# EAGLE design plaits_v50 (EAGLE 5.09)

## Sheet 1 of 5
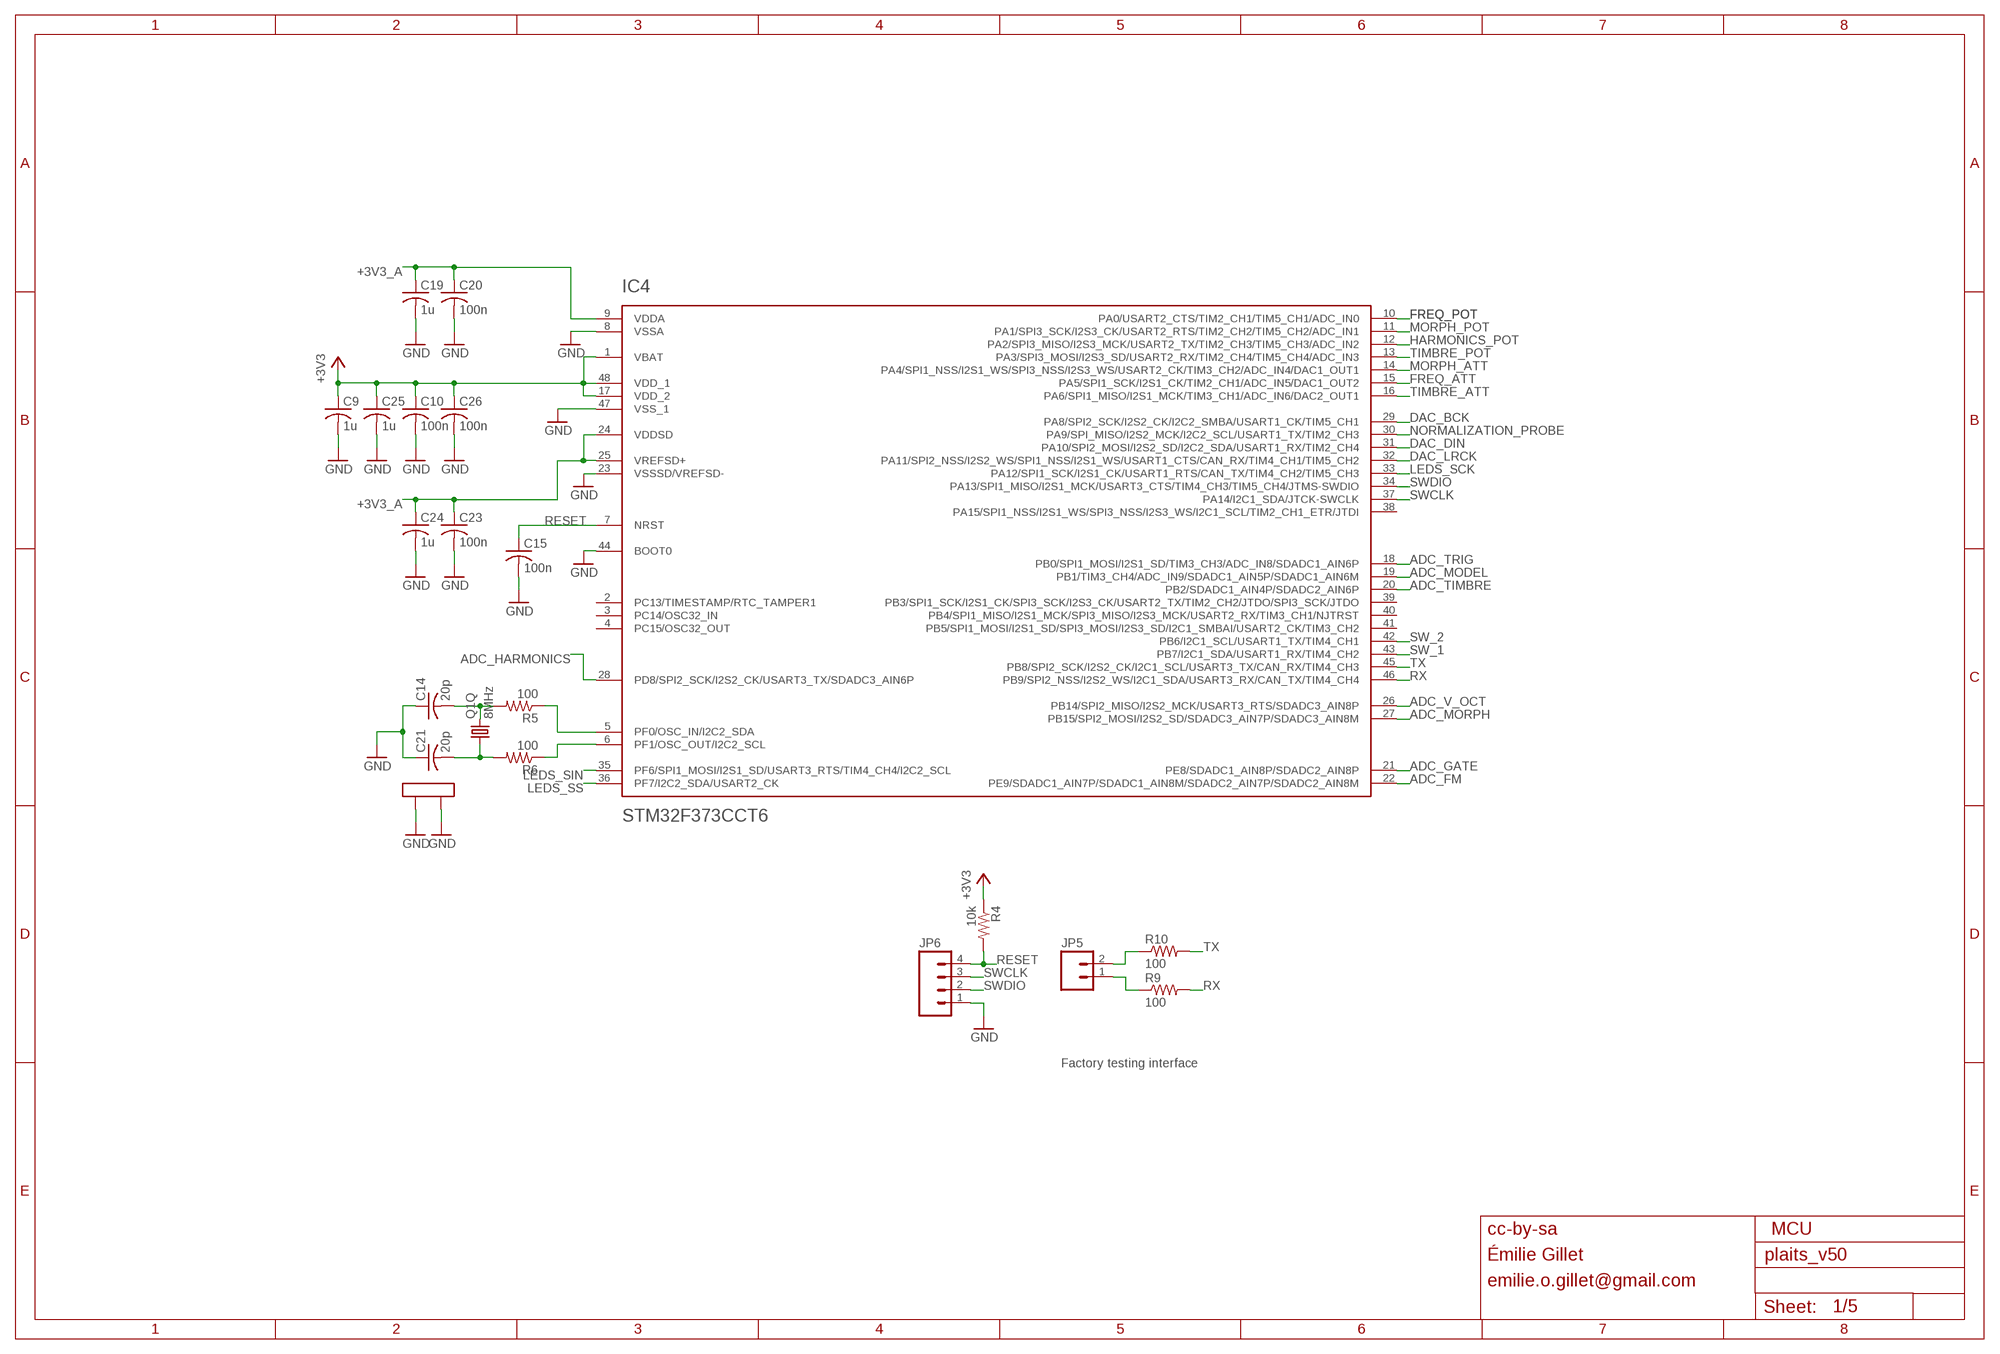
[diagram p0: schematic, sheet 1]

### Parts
C9  1u  C-USC0402  [C0402]
C10  100n  C-USC0402  [C0402]
C14  20p  C-USC0402  [C0402]
C15  100n  C-USC0402  [C0402]
C19  1u  C-USC0402  [C0402]
C20  100n  C-USC0402  [C0402]
C21  20p  C-USC0402  [C0402]
C23  100n  C-USC0402  [C0402]
C24  1u  C-USC0402  [C0402]
C25  1u  C-USC0402  [C0402]
C26  100n  C-USC0402  [C0402]
IC4  STM32F373CCT6  STM32F373C  [LQFP48]
JP5  M02PTH  [1X02]
JP6  M04PTH  [1X04]
Q1  8MHz  CRYSTAL  [CTS406]
R4  10k  R-US_R0402  [R0402]
R5  100  R-US_R0402  [R0402]
R6  100  R-US_R0402  [R0402]
R9  100  R-US_R0402  [R0402]
R10  100  R-US_R0402  [R0402]

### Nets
+3V3: C9.1 C10.1 C25.1 C26.1 IC4.1(VBAT) IC4.17(VDD_2) IC4.48(VDD_1) R4.1 ; also sheet 2,3,4,5
+3V3_A: C19.1 C20.1 C23.1 C24.1 IC4.9(VDDA) IC4.24(VDDSD) IC4.25(VREFSD+) ; also sheet 2,3,4,5
ADC_FM: IC4.22(PE9/SDADC1_AIN7P/SDADC1_AIN8M/SDADC2_AIN7P/SDADC2_AIN8M) ; also sheet 3
ADC_GATE: IC4.21(PE8/SDADC1_AIN8P/SDADC2_AIN8P) ; also sheet 3
ADC_HARMONICS: IC4.28(PD8/SPI2_SCK/I2S2_CK/USART3_TX/SDADC3_AIN6P) ; also sheet 3
ADC_MODEL: IC4.19(PB1/TIM3_CH4/ADC_IN9/SDADC1_AIN5P/SDADC1_AIN6M) ; also sheet 3
ADC_MORPH: IC4.27(PB15/SPI2_MOSI/I2S2_SD/SDADC3_AIN7P/SDADC3_AIN8M) ; also sheet 3
ADC_TIMBRE: IC4.20(PB2/SDADC1_AIN4P/SDADC2_AIN6P) ; also sheet 3
ADC_TRIG: IC4.18(PB0/SPI1_MOSI/I2S1_SD/TIM3_CH3/ADC_IN8/SDADC1_AIN6P) ; also sheet 3
ADC_V_OCT: IC4.26(PB14/SPI2_MISO/I2S2_MCK/USART3_RTS/SDADC3_AIN8P) ; also sheet 3
DAC_BCK: IC4.29(PA8/SPI2_SCK/I2S2_CK/I2C2_SMBA/USART1_CK/TIM5_CH1) ; also sheet 4
DAC_DIN: IC4.31(PA10/SPI2_MOSI/I2S2_SD/I2C2_SDA/USART1_RX/TIM2_CH4) ; also sheet 4
DAC_LRCK: IC4.32(PA11/SPI2_NSS/I2S2_WS/SPI1_NSS/I2S1_WS/USART1_CTS/CAN_RX/TIM4_CH1/TIM5_CH2) ; also sheet 4
FREQ_ATT: IC4.15(PA5/SPI1_SCK/I2S1_CK/TIM2_CH1/ADC_IN5/DAC1_OUT2) ; also sheet 2
FREQ_POT: IC4.10(PA0/USART2_CTS/TIM2_CH1/TIM5_CH1/ADC_IN0) ; also sheet 2
GND: C9.2 C10.2 C14.1 C15.2 C19.2 C20.2 C21.1 C23.2 C24.2 C25.2 C26.2 IC4.8(VSSA) IC4.23(VSSSD/VREFSD-) IC4.44(BOOT0) IC4.47(VSS_1) JP6.1 Q1.2(LID1) Q1.4(LID2) ; also sheet 2,3,4,5
HARMONICS_POT: IC4.12(PA2/SPI3_MISO/I2S3_MCK/USART2_TX/TIM2_CH3/TIM5_CH3/ADC_IN2) ; also sheet 2
LEDS_SCK: IC4.33(PA12/SPI1_SCK/I2S1_CK/USART1_RTS/CAN_TX/TIM4_CH2/TIM5_CH3) ; also sheet 2
LEDS_SIN: IC4.35(PF6/SPI1_MOSI/I2S1_SD/USART3_RTS/TIM4_CH4/I2C2_SCL) ; also sheet 2
LEDS_SS: IC4.36(PF7/I2C2_SDA/USART2_CK) ; also sheet 2
MORPH_ATT: IC4.14(PA4/SPI1_NSS/I2S1_WS/SPI3_NSS/I2S3_WS/USART2_CK/TIM3_CH2/ADC_IN4/DAC1_OUT1) ; also sheet 2
MORPH_POT: IC4.11(PA1/SPI3_SCK/I2S3_CK/USART2_RTS/TIM2_CH2/TIM5_CH2/ADC_IN1) ; also sheet 2
N$7: IC4.5(PF0/OSC_IN/I2C2_SDA) R5.1
N$8: IC4.6(PF1/OSC_OUT/I2C2_SCL) R6.1
N$29: C14.2 Q1.3 R5.2
N$33: JP5.2 R10.1
N$35: C21.2 Q1.1 R6.2
N$51: JP5.1 R9.1
NORMALIZATION_PROBE: IC4.30(PA9/SPI_MISO/I2S2_MCK/I2C2_SCL/USART1_TX/TIM2_CH3) ; also sheet 3
RESET: C15.1 IC4.7(NRST) JP6.4 R4.2
RX: IC4.46(PB9/SPI2_NSS/I2S2_WS/I2C1_SDA/USART3_RX/CAN_TX/TIM4_CH4) R9.2
SW_1: IC4.43(PB7/I2C1_SDA/USART1_RX/TIM4_CH2) ; also sheet 2
SW_2: IC4.42(PB6/I2C1_SCL/USART1_TX/TIM4_CH1) ; also sheet 2
SWCLK: IC4.37(PA14/I2C1_SDA/JTCK-SWCLK) JP6.3
SWDIO: IC4.34(PA13/SPI1_MISO/I2S1_MCK/USART3_CTS/TIM4_CH3/TIM5_CH4/JTMS-SWDIO) JP6.2
TIMBRE_ATT: IC4.16(PA6/SPI1_MISO/I2S1_MCK/TIM3_CH1/ADC_IN6/DAC2_OUT1) ; also sheet 2
TIMBRE_POT: IC4.13(PA3/SPI3_MOSI/I2S3_SD/USART2_RX/TIM2_CH4/TIM5_CH4/ADC_IN3) ; also sheet 2
TX: IC4.45(PB8/SPI2_SCK/I2S2_CK/I2C1_SCL/USART3_TX/CAN_RX/TIM4_CH3) R10.2
Unconnected: IC4.2(PC13/TIMESTAMP/RTC_TAMPER1) IC4.3(PC14/OSC32_IN) IC4.4(PC15/OSC32_OUT) IC4.38(PA15/SPI1_NSS/I2S1_WS/SPI3_NSS/I2S3_WS/I2C1_SCL/TIM2_CH1_ETR/JTDI) IC4.39(PB3/SPI1_SCK/I2S1_CK/SPI3_SCK/I2S3_CK/USART2_TX/TIM2_CH2/JTDO/SPI3_SCK/JTDO) IC4.40(PB4/SPI1_MISO/I2S1_MCK/SPI3_MISO/I2S3_MCK/USART2_RX/TIM3_CH1/NJTRST) IC4.41(PB5/SPI1_MOSI/I2S1_SD/SPI3_MOSI/I2S3_SD/I2C1_SMBAI/USART2_CK/TIM3_CH2)

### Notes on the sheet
- Factory testing interface
- cc-by-sa | MCU
- Émilie Gillet
- emilie.o.gillet@gmail.com

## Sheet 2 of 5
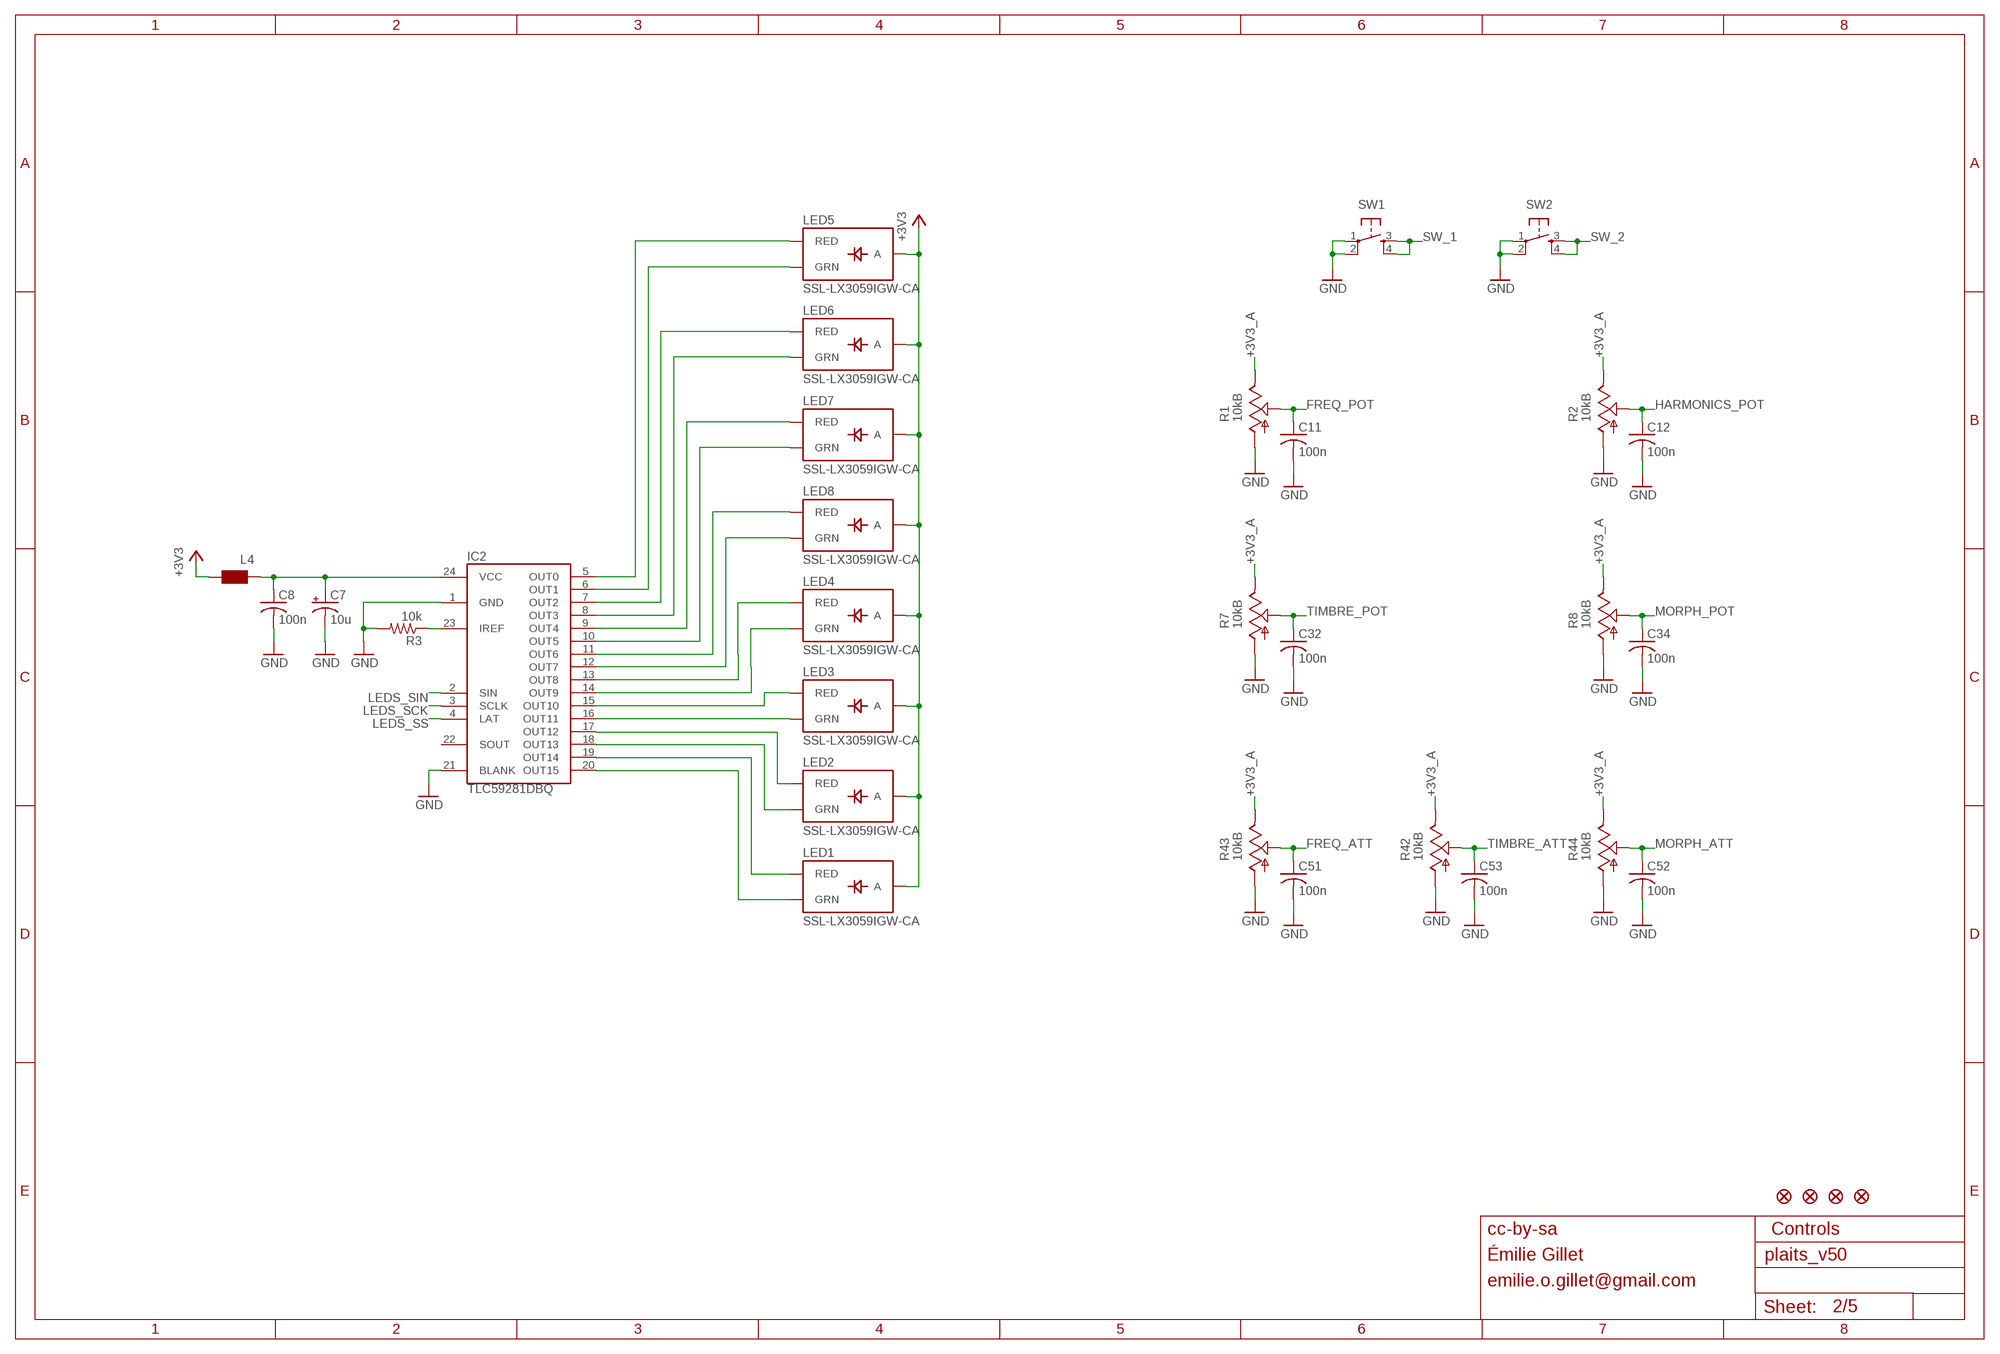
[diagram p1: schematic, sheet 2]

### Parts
C7  10u  CPOL-USA  [PANASONIC_A]
C8  100n  C-USC0402  [C0402]
C11  100n  C-USC0402  [C0402]
C12  100n  C-USC0402  [C0402]
C32  100n  C-USC0402  [C0402]
C34  100n  C-USC0402  [C0402]
C51  100n  C-USC0402  [C0402]
C52  100n  C-USC0402  [C0402]
C53  100n  C-USC0402  [C0402]
IC2  TLC59281DBQ  [TSSOP24_0635]
JP1  FIDUCIAL1X2  [FIDUCIAL-1X2]
JP2  FIDUCIAL1X2  [FIDUCIAL-1X2]
JP3  FIDUCIAL1X2  [FIDUCIAL-1X2]
JP4  FIDUCIAL1X2  [FIDUCIAL-1X2]
L4  WE-CBF_0603  [0603]
LED1  SSL-LX3059IGW-CA  LED-BICOLOR-THROUGHHOLE-CA  [LED-BICOLOR-THROUGHHOLE-LUMEX]
LED2  SSL-LX3059IGW-CA  LED-BICOLOR-THROUGHHOLE-CA  [LED-BICOLOR-THROUGHHOLE-LUMEX]
LED3  SSL-LX3059IGW-CA  LED-BICOLOR-THROUGHHOLE-CA  [LED-BICOLOR-THROUGHHOLE-LUMEX]
LED4  SSL-LX3059IGW-CA  LED-BICOLOR-THROUGHHOLE-CA  [LED-BICOLOR-THROUGHHOLE-LUMEX]
LED5  SSL-LX3059IGW-CA  LED-BICOLOR-THROUGHHOLE-CA  [LED-BICOLOR-THROUGHHOLE-LUMEX]
LED6  SSL-LX3059IGW-CA  LED-BICOLOR-THROUGHHOLE-CA  [LED-BICOLOR-THROUGHHOLE-LUMEX]
LED7  SSL-LX3059IGW-CA  LED-BICOLOR-THROUGHHOLE-CA  [LED-BICOLOR-THROUGHHOLE-LUMEX]
LED8  SSL-LX3059IGW-CA  LED-BICOLOR-THROUGHHOLE-CA  [LED-BICOLOR-THROUGHHOLE-LUMEX]
R1  10kB  POT_USVERTICAL_PS  [ALPS_POT_VERTICAL_PS]
R2  10kB  POT_USVERTICAL_PS  [ALPS_POT_VERTICAL_PS]
R3  10k  R-US_R0402  [R0402]
R7  10kB  POT_USVERTICAL_PS  [ALPS_POT_VERTICAL_PS]
R8  10kB  POT_USVERTICAL_PS  [ALPS_POT_VERTICAL_PS]
R42  10kB  POT_USVERTICAL  [ALPS_POT_VERTICAL]
R43  10kB  POT_USVERTICAL  [ALPS_POT_VERTICAL]
R44  10kB  POT_USVERTICAL  [ALPS_POT_VERTICAL]
SW1  TAC_SWITCHPTH  [TACTILE-PTH]
SW2  TAC_SWITCHPTH  [TACTILE-PTH]

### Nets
+3V3: L4.2 LED1.A LED2.A LED3.A LED4.A LED5.A LED6.A LED7.A LED8.A ; also sheet 1,3,4,5
+3V3_A: R1.P$1(E) R2.P$1(E) R7.P$1(E) R8.P$1(E) R42.P$1(E) R43.P$1(E) R44.P$1(E) ; also sheet 1,3,4,5
FREQ_ATT: C51.1 R43.P$2(S) ; also sheet 1
FREQ_POT: C11.1 R1.P$2(S) ; also sheet 1
GND: C7.- C8.2 C11.2 C12.2 C32.2 C34.2 C51.2 C52.2 C53.2 IC2.1(GND) IC2.21(BLANK) R1.P$3(A) R2.P$3(A) R3.2 R7.P$3(A) R8.P$3(A) R42.P$3(A) R43.P$3(A) R44.P$3(A) SW1.1 SW1.2 SW2.1 SW2.2 ; also sheet 1,3,4,5
HARMONICS_POT: C12.1 R2.P$2(S) ; also sheet 1
LEDS_SCK: IC2.3(SCLK) ; also sheet 1
LEDS_SIN: IC2.2(SIN) ; also sheet 1
LEDS_SS: IC2.4(LAT) ; also sheet 1
MORPH_ATT: C52.1 R44.P$2(S) ; also sheet 1
MORPH_POT: C34.1 R8.P$2(S) ; also sheet 1
N$2: IC2.12(OUT7) LED8.GREEN_C(GRN)
N$5: IC2.11(OUT6) LED8.RED_C(RED)
N$9: IC2.10(OUT5) LED7.GREEN_C(GRN)
N$10: IC2.9(OUT4) LED7.RED_C(RED)
N$11: IC2.8(OUT3) LED6.GREEN_C(GRN)
N$12: IC2.13(OUT8) LED4.RED_C(RED)
N$13: IC2.7(OUT2) LED6.RED_C(RED)
N$14: IC2.14(OUT9) LED4.GREEN_C(GRN)
N$15: IC2.6(OUT1) LED5.GREEN_C(GRN)
N$17: IC2.15(OUT10) LED3.RED_C(RED)
N$18: IC2.16(OUT11) LED3.GREEN_C(GRN)
N$19: IC2.17(OUT12) LED2.RED_C(RED)
N$20: IC2.18(OUT13) LED2.GREEN_C(GRN)
N$21: IC2.19(OUT14) LED1.RED_C(RED)
N$22: IC2.5(OUT0) LED5.RED_C(RED)
N$23: IC2.20(OUT15) LED1.GREEN_C(GRN)
N$27: C7.+ C8.1 IC2.24(VCC) L4.1
N$68: IC2.23(IREF) R3.1
SW_1: SW1.3 SW1.4 ; also sheet 1
SW_2: SW2.3 SW2.4 ; also sheet 1
TIMBRE_ATT: C53.1 R42.P$2(S) ; also sheet 1
TIMBRE_POT: C32.1 R7.P$2(S) ; also sheet 1
Unconnected: IC2.22(SOUT)

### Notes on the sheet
- cc-by-sa | Controls
- Émilie Gillet
- emilie.o.gillet@gmail.com

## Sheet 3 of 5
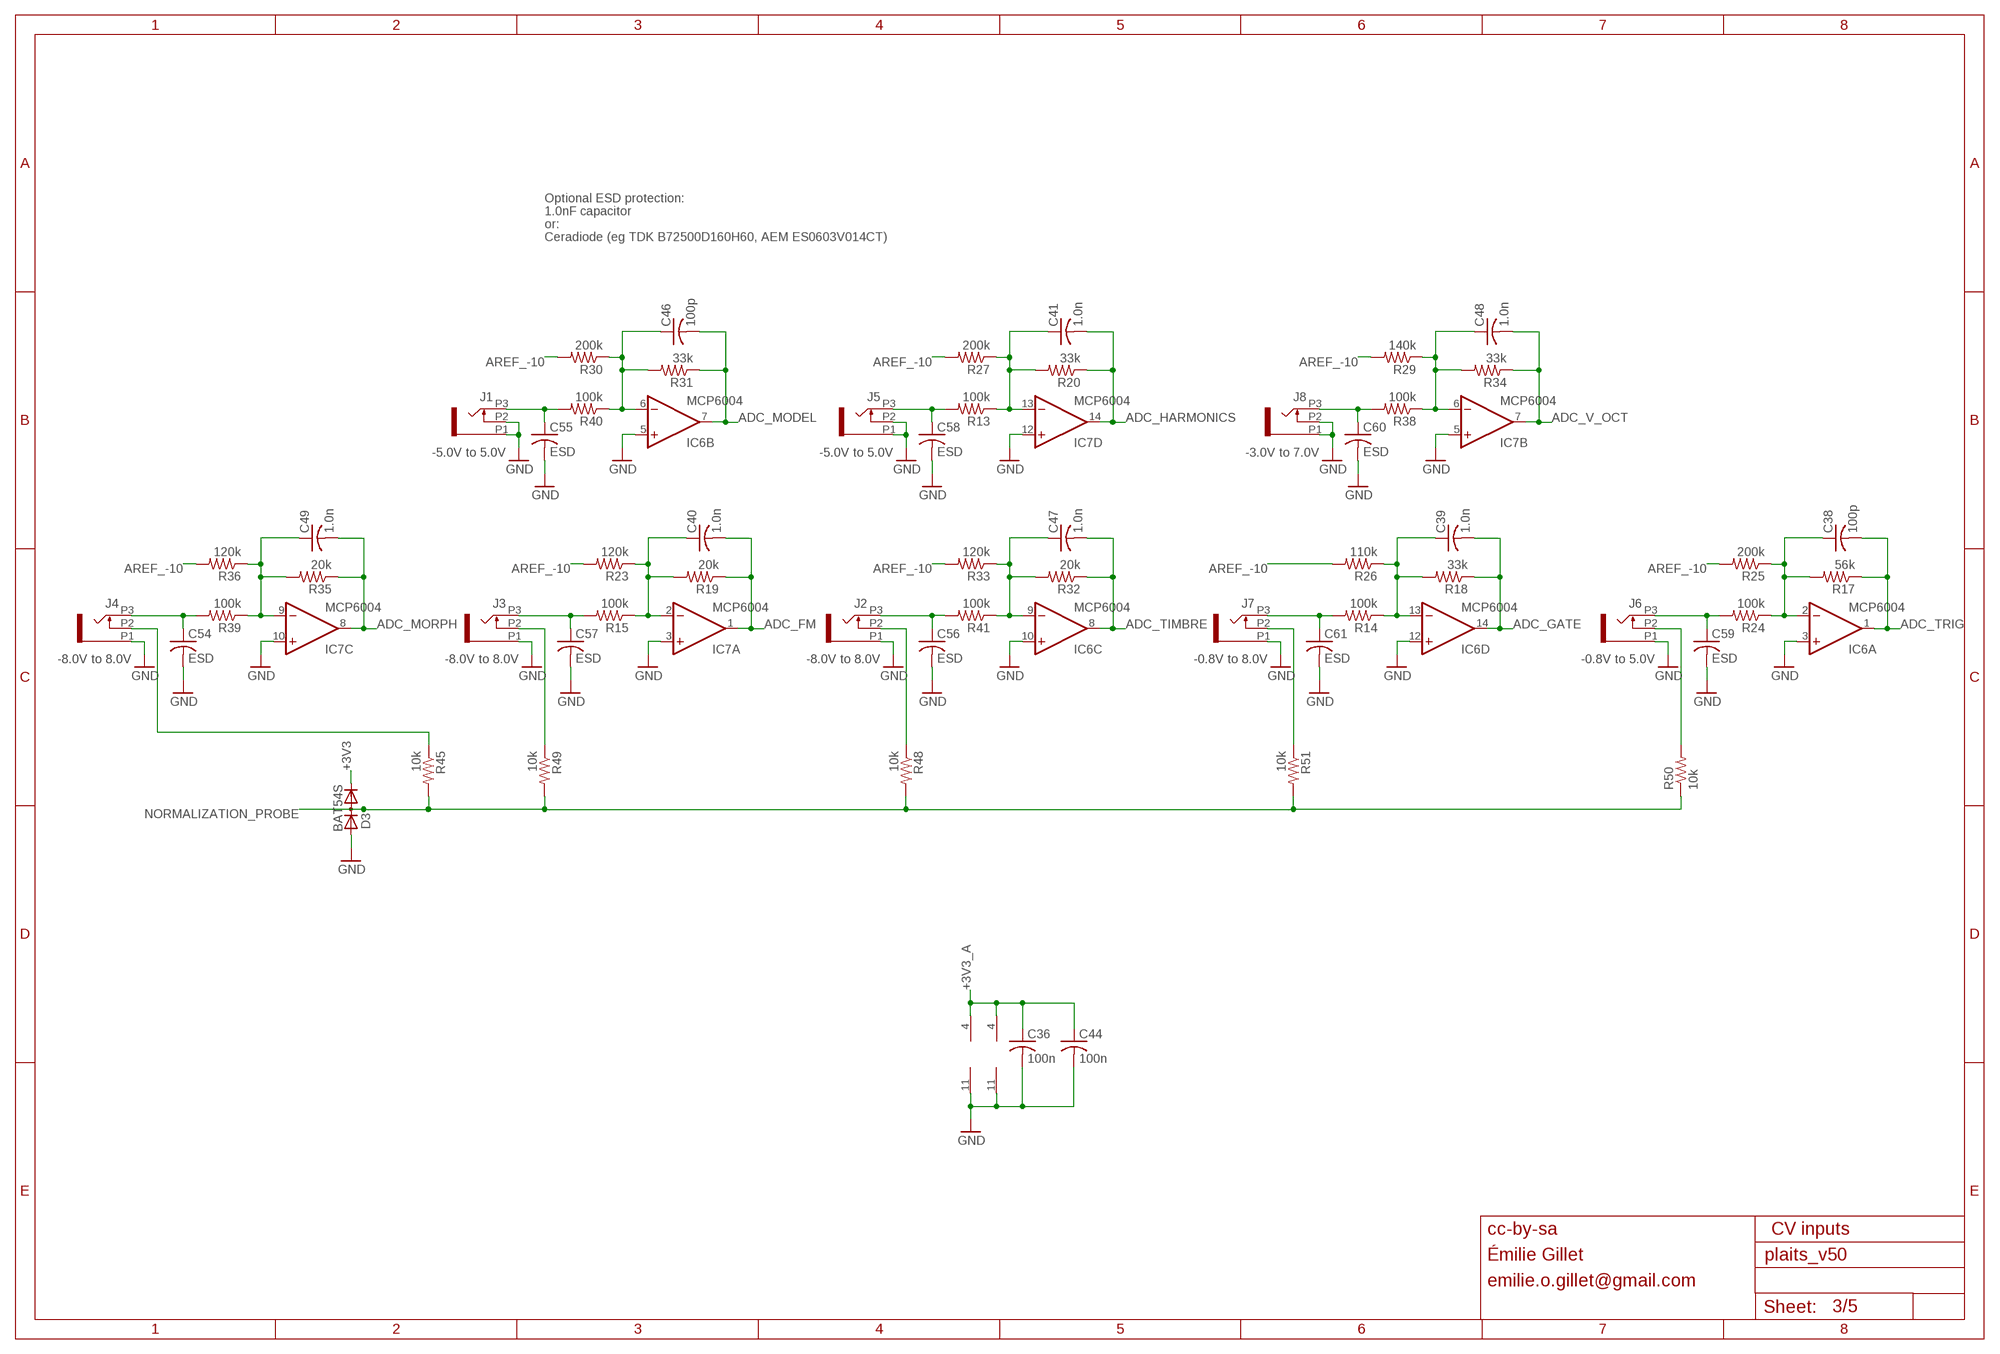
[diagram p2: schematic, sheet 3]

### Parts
C36  100n  C-USC0402  [C0402]
C38  100p  C-USC0402  [C0402]
C39  1.0n  C-USC0402  [C0402]
C40  1.0n  C-USC0402  [C0402]
C41  1.0n  C-USC0402  [C0402]
C44  100n  C-USC0402  [C0402]
C46  100p  C-USC0402  [C0402]
C47  1.0n  C-USC0402  [C0402]
C48  1.0n  C-USC0402  [C0402]
C49  1.0n  C-USC0402  [C0402]
C54  ESD  C-USC0603  [C0603]
C55  ESD  C-USC0603  [C0603]
C56  ESD  C-USC0603  [C0603]
C57  ESD  C-USC0603  [C0603]
C58  ESD  C-USC0603  [C0603]
C59  ESD  C-USC0603  [C0603]
C60  ESD  C-USC0603  [C0603]
C61  ESD  C-USC0603  [C0603]
D3  BAT54S  DIODE_2CACA-SOT23  [SOT23]
IC6  MCP6004  TL074PW  [TSSOP14_065]
IC7  MCP6004  TL074PW  [TSSOP14_065]
J1  PJ301_THONKICONN6  [WQP_PJ_301M6]
J2  PJ301_THONKICONN6  [WQP_PJ_301M6]
J3  PJ301_THONKICONN6  [WQP_PJ_301M6]
J4  PJ301_THONKICONN6  [WQP_PJ_301M6]
J5  PJ301_THONKICONN6  [WQP_PJ_301M6]
J6  PJ301_THONKICONN6  [WQP_PJ_301M6]
J7  PJ301_THONKICONN6  [WQP_PJ_301M6]
J8  PJ301_THONKICONN6  [WQP_PJ_301M6]
R13  100k  R-US_R0402  [R0402]
R14  100k  R-US_R0402  [R0402]
R15  100k  R-US_R0402  [R0402]
R17  56k  R-US_R0402  [R0402]
R18  33k  R-US_R0402  [R0402]
R19  20k  R-US_R0402  [R0402]
R20  33k  R-US_R0402  [R0402]
R23  120k  R-US_R0402  [R0402]
R24  100k  R-US_R0402  [R0402]
R25  200k  R-US_R0402  [R0402]
R26  110k  R-US_R0402  [R0402]
R27  200k  R-US_R0402  [R0402]
R29  140k  R-US_R0402  [R0402]
R30  200k  R-US_R0402  [R0402]
R31  33k  R-US_R0402  [R0402]
R32  20k  R-US_R0402  [R0402]
R33  120k  R-US_R0402  [R0402]
R34  33k  R-US_R0402  [R0402]
R35  20k  R-US_R0402  [R0402]
R36  120k  R-US_R0402  [R0402]
R38  100k  R-US_R0402  [R0402]
R39  100k  R-US_R0402  [R0402]
R40  100k  R-US_R0402  [R0402]
R41  100k  R-US_R0402  [R0402]
R45  10k  R-US_R0402  [R0402]
R48  10k  R-US_R0402  [R0402]
R49  10k  R-US_R0402  [R0402]
R50  10k  R-US_R0402  [R0402]
R51  10k  R-US_R0402  [R0402]

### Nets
+3V3: D3.2(C) ; also sheet 1,2,4,5
+3V3_A: C36.1 C44.1 IC6.4(P:V+) IC7.4(P:V+) ; also sheet 1,2,4,5
ADC_FM: C40.2 IC7.1(A:OUT) R19.1 ; also sheet 1
ADC_GATE: C39.2 IC6.14(D:OUT) R18.1 ; also sheet 1
ADC_HARMONICS: C41.2 IC7.14(D:OUT) R20.1 ; also sheet 1
ADC_MODEL: C46.2 IC6.7(B:OUT) R31.1 ; also sheet 1
ADC_MORPH: C49.2 IC7.8(C:OUT) R35.1 ; also sheet 1
ADC_TIMBRE: C47.2 IC6.8(C:OUT) R32.1 ; also sheet 1
ADC_TRIG: C38.2 IC6.1(A:OUT) R17.1 ; also sheet 1
ADC_V_OCT: C48.2 IC7.7(B:OUT) R34.1 ; also sheet 1
AREF_-10: R23.2 R25.2 R26.2 R27.2 R29.2 R30.2 R33.2 R36.2 ; also sheet 5
FM_IN: C57.1 J3.P3 R15.2
GATE_IN: C61.1 J7.P3 R14.2
GATE_IN1: C59.1 J6.P3 R24.2
GND: C36.2 C44.2 C54.2 C55.2 C56.2 C57.2 C58.2 C59.2 C60.2 C61.2 D3.1(A) IC6.3(A:+IN) IC6.5(B:+IN) IC6.10(C:+IN) IC6.11(P:V-) IC6.12(D:+IN) IC7.3(A:+IN) IC7.5(B:+IN) IC7.10(C:+IN) IC7.11(P:V-) IC7.12(D:+IN) J1.P1 J1.P2 J2.P1 J3.P1 J4.P1 J5.P1 J5.P2 J6.P1 J7.P1 J8.P1 J8.P2 ; also sheet 1,2,4,5
HARMONICS_IN: C58.1 J5.P3 R13.2
MODEL_IN: C55.1 J1.P3 R40.2
MORPH_IN: C54.1 J4.P3 R39.2
N$3: J6.P2 R50.2
N$4: C38.1 IC6.2(A:-IN) R17.2 R24.1 R25.1
N$24: J3.P2 R49.1
N$25: J2.P2 R48.1
N$26: J4.P2 R45.1
N$28: C39.1 IC6.13(D:-IN) R14.1 R18.2 R26.1
N$30: C48.1 IC7.6(B:-IN) R29.1 R34.2 R38.1
N$31: C56.1 J2.P3 R41.2
N$32: C49.1 IC7.9(C:-IN) R35.2 R36.1 R39.1
N$34: C40.1 IC7.2(A:-IN) R15.1 R19.2 R23.1
N$36: J7.P2 R51.1
N$37: C46.1 IC6.6(B:-IN) R30.1 R31.2 R40.1
N$39: C47.1 IC6.9(C:-IN) R32.2 R33.1 R41.1
N$41: C41.1 IC7.13(D:-IN) R13.1 R20.2 R27.1
NORMALIZATION_PROBE: D3.3(AC) R45.2 R48.2 R49.2 R50.1 R51.2 ; also sheet 1
V_OCT_IN: C60.1 J8.P3 R38.2

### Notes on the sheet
- Optional ESD protection:
- 1.0nF capacitor
- or:
- Ceradiode (eg TDK B72500D160H60, AEM ES0603V014CT)
- -5.0V to 5.0V | -5.0V to 5.0V | -3.0V to 7.0V
- -8.0V to 8.0V | -8.0V to 8.0V | -8.0V to 8.0V | -0.8V to 8.0V | -0.8V to 5.0V
- cc-by-sa | CV inputs
- Émilie Gillet
- emilie.o.gillet@gmail.com

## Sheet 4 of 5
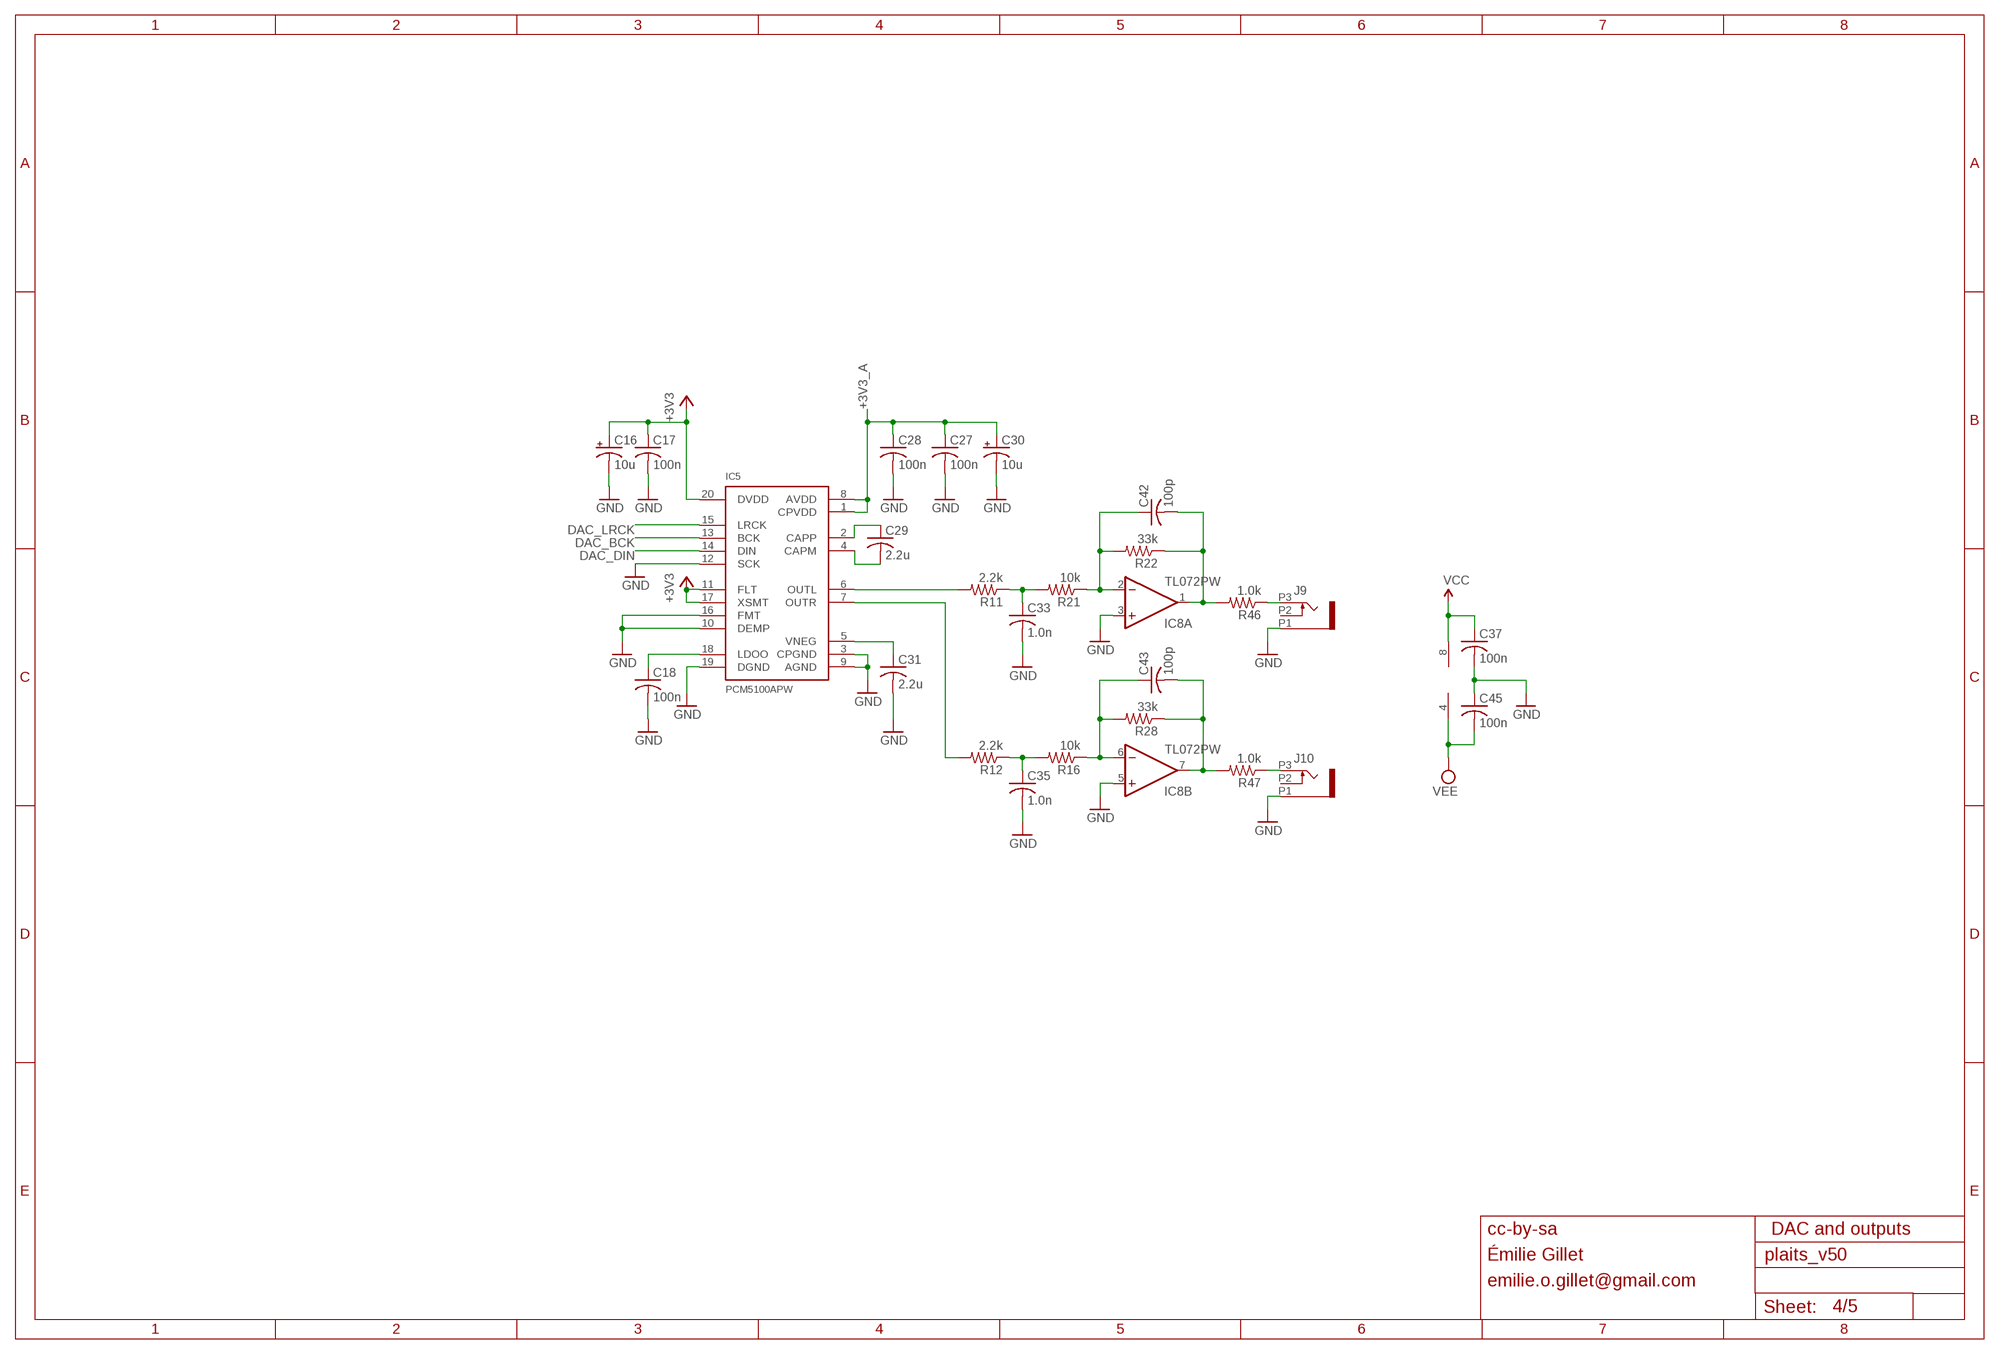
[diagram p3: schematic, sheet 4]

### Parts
C16  10u  CPOL-USA  [PANASONIC_A]
C17  100n  C-USC0402  [C0402]
C18  100n  C-USC0402  [C0402]
C27  100n  C-USC0402  [C0402]
C28  100n  C-USC0402  [C0402]
C29  2.2u  C-USC0805  [C0805]
C30  10u  CPOL-USA  [PANASONIC_A]
C31  2.2u  C-USC0805  [C0805]
C33  1.0n  C-USC0402  [C0402]
C35  1.0n  C-USC0402  [C0402]
C37  100n  C-USC0402  [C0402]
C42  100p  C-USC0402  [C0402]
C43  100p  C-USC0402  [C0402]
C45  100n  C-USC0402  [C0402]
IC5  PCM5100APW  PCM5100PW  [SSOP20]
IC8  TL072PW  [TSSOP08]
J9  PJ301_THONKICONN6  [WQP_PJ_301M6]
J10  PJ301_THONKICONN6  [WQP_PJ_301M6]
R11  2.2k  R-US_R0402  [R0402]
R12  2.2k  R-US_R0402  [R0402]
R16  10k  R-US_R0402  [R0402]
R21  10k  R-US_R0402  [R0402]
R22  33k  R-US_R0402  [R0402]
R28  33k  R-US_R0402  [R0402]
R46  1.0k  R-US_R0603  [R0603]
R47  1.0k  R-US_R0603  [R0603]

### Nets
+3V3: C16.+ C17.1 IC5.11(FLT) IC5.17(XSMT) IC5.20(DVDD) ; also sheet 1,2,3,5
+3V3_A: C27.1 C28.1 C30.+ IC5.1(CPVDD) IC5.8(AVDD) ; also sheet 1,2,3,5
DAC_BCK: IC5.13(BCK) ; also sheet 1
DAC_DIN: IC5.14(DIN) ; also sheet 1
DAC_LRCK: IC5.15(LRCK) ; also sheet 1
GND: C16.- C17.2 C18.2 C27.2 C28.2 C30.- C31.2 C33.2 C35.2 C37.2 C45.1 IC5.3(CPGND) IC5.9(AGND) IC5.10(DEMP) IC5.12(SCK) IC5.16(FMT) IC5.19(DGND) IC8.3(A:+IN) IC8.5(B:+IN) J9.P1 J10.P1 ; also sheet 1,2,3,5
N$6: C29.1 IC5.2(CAPP)
N$16: C29.2 IC5.4(CAPM)
N$43: IC5.6(OUTL) R11.2
N$46: C33.1 R11.1 R21.2
N$47: C35.1 R12.1 R16.2
N$48: C31.1 IC5.5(VNEG)
N$54: C18.1 IC5.18(LDOO)
N$55: IC5.7(OUTR) R12.2
N$58: C43.1 IC8.6(B:-IN) R16.1 R28.2
N$60: C43.2 IC8.7(B:OUT) R28.1 R47.2
N$62: C42.1 IC8.2(A:-IN) R21.1 R22.2
N$63: C42.2 IC8.1(A:OUT) R22.1 R46.2
N$65: J9.P3 R46.1
N$69: J10.P3 R47.1
VCC: C37.1 IC8.8(P:V+) ; also sheet 5
VEE: C45.2 IC8.4(P:V-) ; also sheet 5
Unconnected: J9.P2 J10.P2

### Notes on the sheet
- cc-by-sa | DAC and outputs
- Émilie Gillet
- emilie.o.gillet@gmail.com

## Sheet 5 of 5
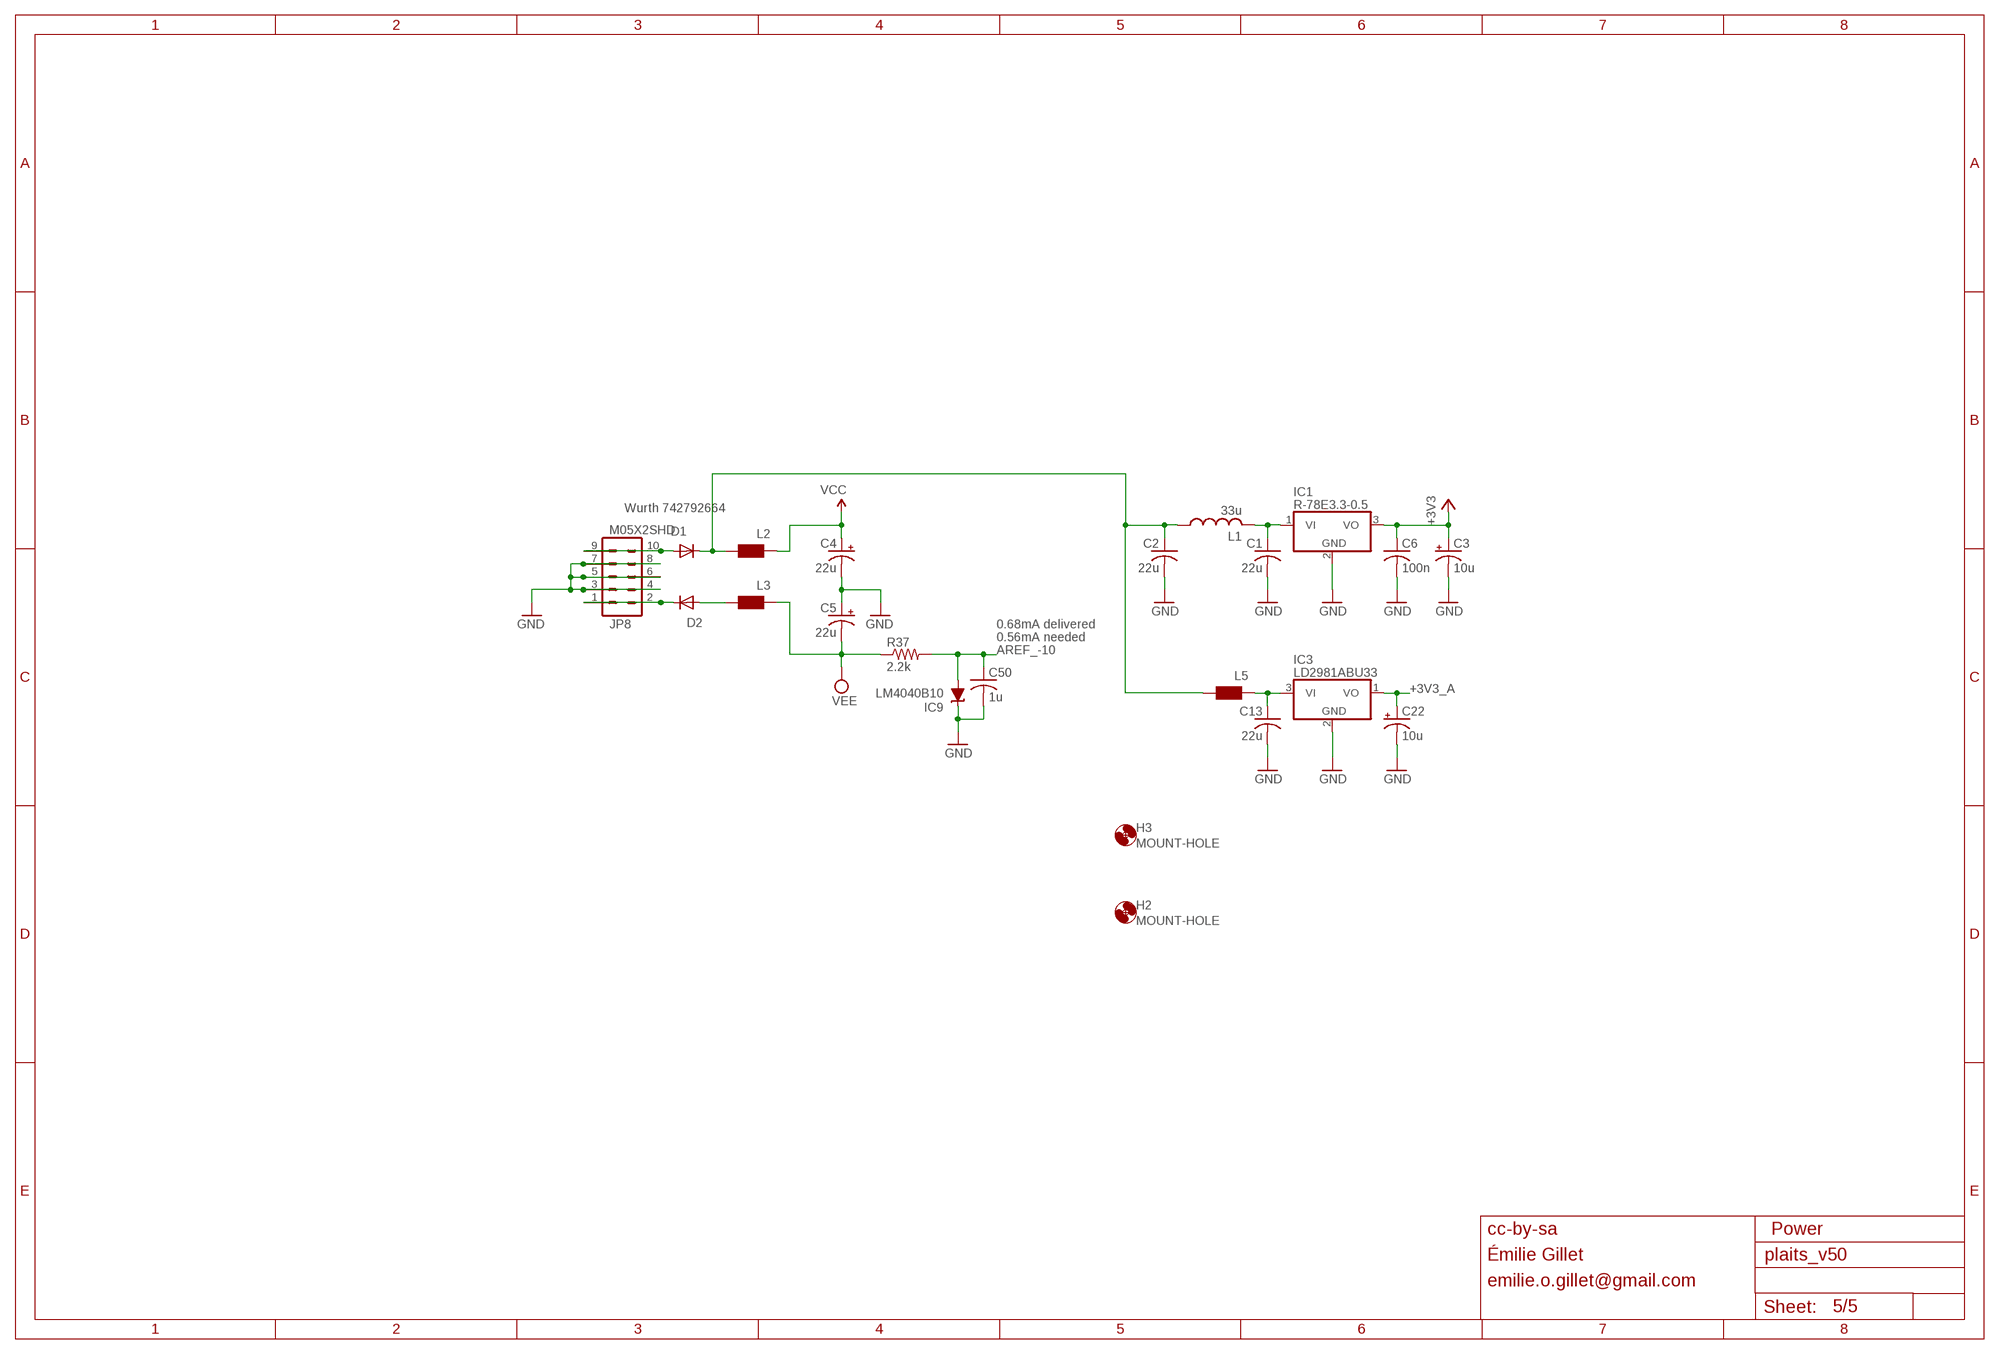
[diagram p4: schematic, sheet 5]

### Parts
C1  22u  C-USC1206  [C1206]
C2  22u  C-USC1206  [C1206]
C3  10u  CPOL-USA  [PANASONIC_A]
C4  22u  CPOL-USB  [PANASONIC_B]
C5  22u  CPOL-USB  [PANASONIC_B]
C6  100n  C-USC0402  [C0402]
C13  22u  C-USC1206  [C1206]
C22  10u  CPOL-USA  [PANASONIC_A]
C50  1u  C-USC0402  [C0402]
D1  1N5819HW  DIODE-SOD123  [SOD123]
D2  1N5819HW  DIODE-SOD123  [SOD123]
H2  MOUNT-HOLE  MOUNT-HOLE3.0TINY  [3,0TINY]
H3  MOUNT-HOLE  MOUNT-HOLE3.0TINY  [3,0TINY]
IC1  R-78E3.3-0.5  WE173950378  [WE78]
IC3  LD2981ABU33  LD2981ABU  [SOT89]
IC9  LM4040B10  LM4041B12DBZ  [DBZ_R-PDSO-G3]
JP8  M05X2SHD  [2X5-SHROUDED]
L1  33u  L-USL2012C  [L2012C]
L2  WE-CBF_0603  [0603]
L3  WE-CBF_0603  [0603]
L5  WE-CBF_0603  [0603]
R37  2.2k  R-US_R0402  [R0402]

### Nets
+3V3: C3.+ C6.1 IC1.3(VO) ; also sheet 1,2,3,4
+3V3_A: C22.+ IC3.1(VO) ; also sheet 1,2,3,4
AREF_-10: C50.1 IC9.2(A) R37.2 ; also sheet 3
GND: C1.2 C2.2 C3.- C4.- C5.+ C6.2 C13.2 C22.- C50.2 IC1.2(GND) IC3.2(GND) IC9.1(C) JP8.3 JP8.4 JP8.5 JP8.6 JP8.7 JP8.8 ; also sheet 1,2,3,4
N$1: C1.1 IC1.1(VI) L1.2
N$38: D2.A L3.2
N$40: C2.1 D1.C L1.1 L2.2 L5.2
N$42: C13.1 IC3.3(VI) L5.1
N$56: D1.A JP8.9 JP8.10
N$64: D2.C JP8.1 JP8.2
VCC: C4.+ L2.1 ; also sheet 4
VEE: C5.- L3.1 R37.1 ; also sheet 4

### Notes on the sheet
- Wurth 742792664
- 0.68mA delivered
- 0.56mA needed
- cc-by-sa | Power
- Émilie Gillet
- emilie.o.gillet@gmail.com

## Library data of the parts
C1 C2 C6 C8-C15 C17-C21 C23-C29 C31-C61 = rcl:C-US: CAPACITOR, American symbol
C3-C5 C7 C16 C22 C30 = rcl:CPOL-US: POLARIZED CAPACITOR, American symbol
D1 D2 = diode:DIODE-: DIODE
D3 = diode:DIODE_2CACA-: 2 Diodes - Cathode-Anode|Cathode-Anode
H2 H3 = og-holes:MOUNT-HOLE: MOUNTING HOLE with drill center marker
IC1 = og-vreg:WE173950378
IC2 = og-ics:TLC59281
IC3 = og-vreg:LD2981
IC4 = og-stm32f2:STM32F373C
IC5 = og-dac:PCM5100
IC6 IC7 = og-linear:TL074: OP AMP
IC8 = og-linear:TL072: OP AMP
IC9 = texas:LM4041: PRECISION MICROPOWER SHUNT VOLTAGE REFERENCE
J1-J10 = og-pj301_variations:PJ301_THONKICONN
JP1-JP4 = SparkFun:FIDUCIAL: Fiducial Alignment Points
JP5 = SparkFun:M02: Header 2
JP6 = SparkFun:M04: Header 4 Standard 4-pin 0.1" header. Use with straight break away headers (SKU : PRT-00116), right angle break away headers (PRT-00553), swiss pins (PRT-00743), machine pins (PRT-00117), and female headers (PRT-00115). Molex polarized connector foot print use with SKU : PRT-08231 with associated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
JP8 = og-header:M05X2: Header 5x2 Standard 10-pin dual row 0.1" header. Commonly used with AVR-ISP. Use with Spark Fun Electronics SKU: PRT-00778
L1 = og-rcl:L-US
L2-L5 = wuerth-elektronik:WE-CBF: SMD EMI Suppression Ferrite Beads
LED1-LED8 = og-leds:LED-BICOLOR-THROUGHHOLE-CA
Q1 = og-crystal:CRYSTAL: Crystal with 2 extra terminals for the metal LID (Abracon ABMM2 for example)
R1 R2 R7 R8 R42-R44 = og-pots:POT_US
R3-R6 R9-R41 R45-R51 = rcl:R-US_: RESISTOR, American symbol
SW1 SW2 = SparkFun:TAC_SWITCH: Momentary Switch Button commonly used for reset or general input. Spark Fun Electronics SKU : COM-00097

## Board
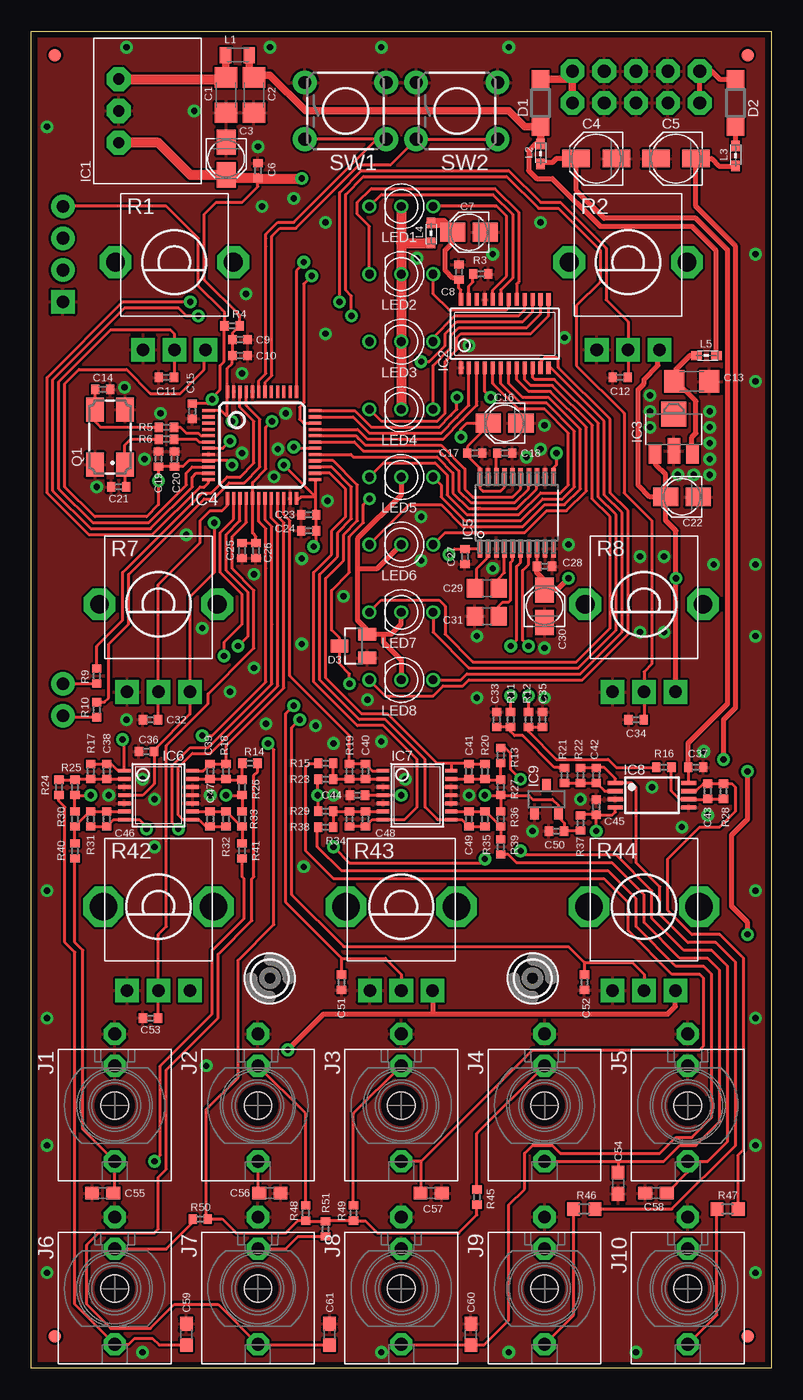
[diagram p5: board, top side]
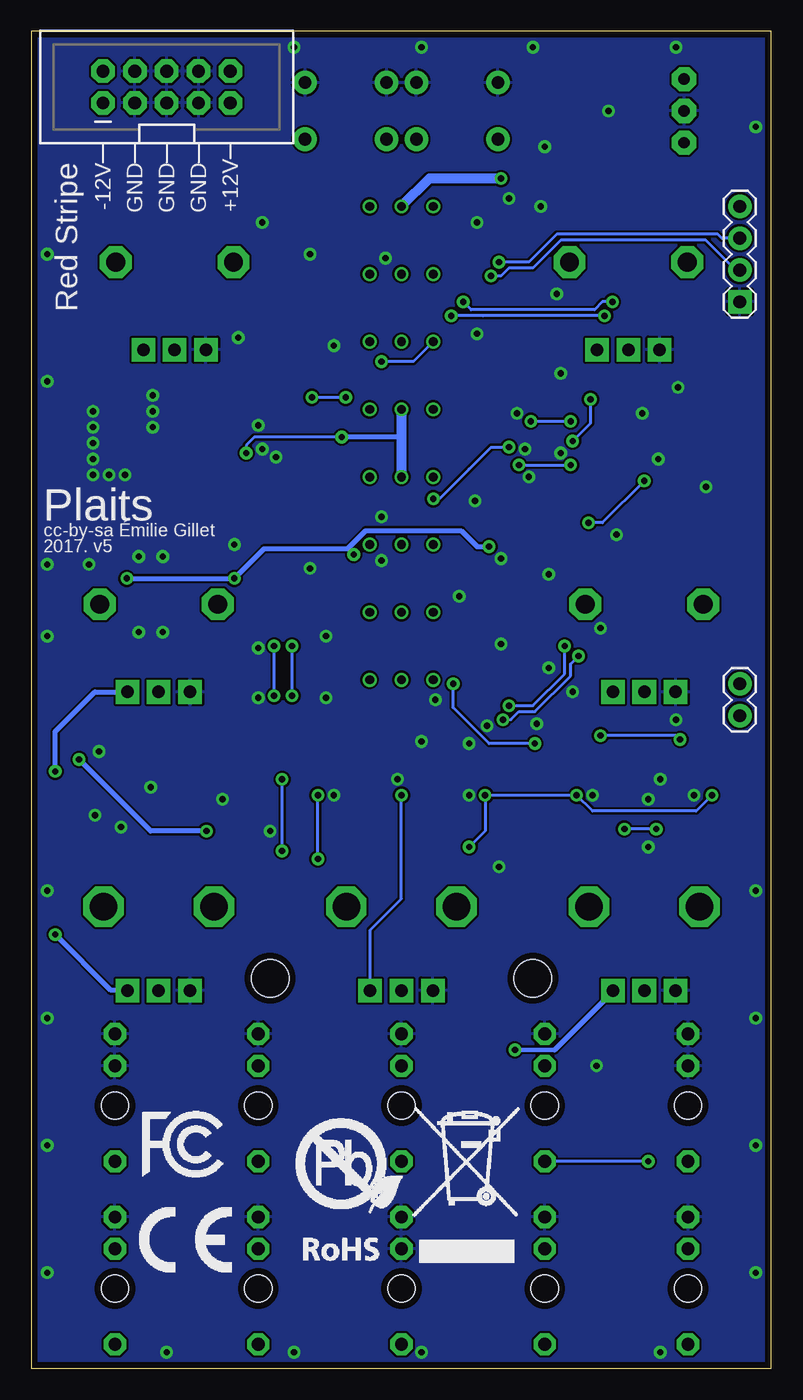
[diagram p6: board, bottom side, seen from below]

Size 59.03 x 106.68 mm. Coordinates in mm from the lower left corner, seen from the top.
Outline: 59.03,0 0,0 0,106.68 59.03,106.68 59.03,0
Copper layers (1*16): Top 0.035mm / dielectric 1.5mm / Bottom 0.035mm
Design rules "PCBCart-Standard": minimum track width 8mil, minimum drill 0.4mm, track to track 7mil, track to pad 7mil, pad to pad 7mil, via to via 7mil, smd to smd 7mil, copper to edge 20mil, drill to drill 8mil, minimum pad ring 8mil, minimum via ring 10mil, stop-mask expansion 3mil, vias tented up to drill 25mil, thermal gap 8mil

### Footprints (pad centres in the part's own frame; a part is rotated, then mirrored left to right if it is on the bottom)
C1206 = smd 1.6 x 1.8: 1 -1.4,0; 2 1.4,0
PANASONIC_A = smd 2 x 1.5: + 1.3,0; - -1.3,0
PANASONIC_B = smd 2.2 x 1.4: + 1.6,0; - -1.6,0
C0402 = smd 0.65 x 0.75: 1 -0.6,0; 2 0.6,0
C0805 = smd 1.3 x 1.5: 1 -0.95,0; 2 0.95,0
C0603 = smd 1.1 x 1: 1 -0.85,0; 2 0.85,0
SOD123 = smd 1.4 x 1.4: A 1.9,0; C -1.9,0
SOT23 = smd 1 x 1.4: 1 -0.95,-1.1; 2 0.95,-1.1; 3 0,1.1
3,0TINY = hole 3: 0,0
WE78 = drill 0.9 pad 1.93 octagon: 1 -2.54,0; 2 0,0; 3 2.54,0
TSSOP24_0635 = smd 0.33 x 1: 1 -3.493,-2.725; 2 -2.857,-2.725; 3 -2.223,-2.725; 4 -1.587,-2.725; 5 -0.953,-2.725; 6 -0.318,-2.725; 7 0.318,-2.725; 8 0.953,-2.725; 9 1.587,-2.725; 10 2.223,-2.725; 11 2.857,-2.725; 12 3.493,-2.725; 13 3.493,2.725; 14 2.857,2.725; 15 2.223,2.725; 16 1.587,2.725; 17 0.953,2.725; 18 0.318,2.725; 19 -0.318,2.725; 20 -0.953,2.725; 21 -1.587,2.725; 22 -2.223,2.725; 23 -2.857,2.725; 24 -3.493,2.725
SOT89 = smd 1 x 1.5: 1 -1.499,-1.981; 3 1.499,-1.981 | smd 1 x 2: 2 0,-1.727 | smd 2 x 2: 2@1 0,1.194
LQFP48 = smd 0.254 x 1: 1 -2.75,-4.25; 2 -2.25,-4.25; 3 -1.75,-4.25; 4 -1.25,-4.25; 5 -0.75,-4.25; 6 -0.25,-4.25; 7 0.25,-4.25; 8 0.75,-4.25; 9 1.25,-4.25; 10 1.75,-4.25; 11 2.25,-4.25; 12 2.75,-4.25; 25 2.75,4.25; 26 2.25,4.25; 27 1.75,4.25; 28 1.25,4.25; 29 0.75,4.25; 30 0.25,4.25; 31 -0.25,4.25; 32 -0.75,4.25; 33 -1.25,4.25; 34 -1.75,4.25; 35 -2.25,4.25; 36 -2.75,4.25 | smd 1 x 0.254: 13 4.25,-2.75; 14 4.25,-2.25; 15 4.25,-1.75; 16 4.25,-1.25; 17 4.25,-0.75; 18 4.25,-0.25; 19 4.25,0.25; 20 4.25,0.75; 21 4.25,1.25; 22 4.25,1.75; 23 4.25,2.25; 24 4.25,2.75; 37 -4.25,2.75; 38 -4.25,2.25; 39 -4.25,1.75; 40 -4.25,1.25; 41 -4.25,0.75; 42 -4.25,0.25; 43 -4.25,-0.25; 44 -4.25,-0.75; 45 -4.25,-1.25; 46 -4.25,-1.75; 47 -4.25,-2.25; 48 -4.25,-2.75
SSOP20 = smd 1.422 x 0.356: 1 -2.845,2.936; 2 -2.845,2.276; 3 -2.845,1.615; 4 -2.845,0.98; 5 -2.845,0.32; 6 -2.845,-0.315; 7 -2.845,-0.98; 8 -2.845,-1.615; 9 -2.845,-2.276; 10 -2.845,-2.936; 11 2.845,-2.936; 12 2.845,-2.276; 13 2.845,-1.615; 14 2.845,-0.98; 15 2.845,-0.315; 16 2.845,0.32; 17 2.845,0.98; 18 2.845,1.615; 19 2.845,2.276; 20 2.845,2.936
TSSOP14_065 = smd 0.305 x 0.991: 1 -1.95,-2.718; 2 -1.3,-2.718; 3 -0.65,-2.718; 4 0,-2.718; 5 0.65,-2.718; 6 1.3,-2.718; 7 1.95,-2.718; 8 1.95,2.718; 9 1.3,2.718; 10 0.65,2.718; 11 0,2.718; 12 -0.65,2.718; 13 -1.3,2.718; 14 -1.95,2.718
TSSOP08 = smd 0.35 x 1.2: 1 -0.975,-2.925; 2 -0.325,-2.925; 3 0.325,-2.925; 4 0.975,-2.925; 5 0.975,2.925; 6 0.325,2.925; 7 -0.325,2.925; 8 -0.975,2.925
DBZ_R-PDSO-G3 = smd 0.7 x 1: 1 -0.95,-1.1; 2 0.95,-1.1; 3 0,1.1
WQP_PJ_301M6 = drill 1.016 pad 1.778 octagon: P1 0,-5.715; P2 0,-3.175; P3 0,4.445 | hole 2.2: 0,0
FIDUCIAL-1X2 = smd 1 x 1: 1 0,0
1X02 = drill 1.016 pad 1.88 round: 1 0,0; 2 2.54,0
1X04 = drill 1.016 pad 1.88 square: 1 0,0 | drill 1.016 pad 1.88 round: 2 2.54,0; 3 5.08,0; 4 7.62,0
2X5-SHROUDED = drill 1.016 pad 1.88 octagon: 1 -1.27,5.08; 2 1.27,5.08; 3 -1.27,2.54; 4 1.27,2.54; 5 -1.27,0; 6 1.27,0; 7 -1.27,-2.54; 8 1.27,-2.54; 9 -1.27,-5.08; 10 1.27,-5.08
L2012C = smd 0.9 x 1.25: 1 -0.9,0; 2 1,0
0603 = smd 0.85 x 0.7: 1 -0.9,0; 2 0.7,0
LED-BICOLOR-THROUGHHOLE-LUMEX = drill 0.7 round: A 0,0; GREEN_C 2.54,0; RED_C -2.54,0
CTS406 = smd 1.9 x 1.4: 1 -2.2,-1.2; 2 2.2,-1.2; 3 2.2,1.2; 4 -2.2,1.2
ALPS_POT_VERTICAL_PS = drill 1 pad 1.88 square: P$1 -2.5,7; P$2 0,7; P$3 2.5,7 | drill 1.5 pad 2.54 octagon: P$4 -4.7,0; P$5 4.7,0
R0402 = smd 0.65 x 0.75: 1 -0.6,0; 2 0.6,0
ALPS_POT_VERTICAL = drill 1 pad 1.88 square: P$1 -2.5,6.7; P$2 0,6.7; P$3 2.5,6.7 | drill 2.2 pad 3.175 octagon: P$4 -4.4,0; P$5 4.4,0
R0603 = smd 1 x 1.1: 1 -0.85,0; 2 0.85,0
TACTILE-PTH = drill 1.016 pad 1.88 round: 1 -3.251,2.261; 2 3.251,2.261; 3 -3.251,-2.261; 4 3.251,-2.261

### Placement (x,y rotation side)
C1  15.54,101.6 270 top
C2  17.76,101.6 270 top
C3  15.54,96.52 270 top
C4  45.06,96.52 180 top
C5  51.41,96.52 180 top
C6  18.08,95.57 90 top
C7  34.91,90.65 180 top
C8  34.11,87.47 90 top
C9  16.65,82.07 0 top
C10  16.65,80.8 0 top
C11  10.78,79.06 180 top
C12  46.97,79.06 180 top
C13  52.68,78.74 0 top
C14  5.7,78.11 180 top
C15  12.84,76.36 270 top
C16  37.76,75.41 180 top
C17  35.38,73.03 0 top
C18  37.76,73.02 0 top
C19  10.14,72.55 90 top
C20  11.41,72.55 90 top
C21  6.97,70.33 0 top
C22  51.89,69.53 180 top
C23  22.13,68.1 180 top
C24  22.13,66.83 180 top
C25  16.81,65.25 270 top
C26  17.92,65.25 270 top
C27  34.59,64.77 270 top
C28  40.94,63.98 0 top
C29  36.33,62.23 0 top
C30  40.94,60.8 90 top
C31  36.33,60.01 180 top
C32  9.51,51.75 180 top
C33  37.13,51.75 90 top
C34  48.24,51.75 180 top
C35  40.78,51.75 90 top
C36  9.19,49.21 180 top
C37  53,47.94 0 top
C38  6.01,47.62 90 top
C39  14.27,47.62 90 top
C40  26.65,47.62 90 top
C41  34.9,47.62 90 top
C42  45.06,47.31 90 top
C43  53.95,46.04 90 top
C44  26.02,45.72 180 top
C45  45.06,44.77 270 top
C46  6.01,43.81 270 top
C47  14.27,43.81 270 top
C48  26.65,43.81 270 top
C49  34.9,43.81 270 top
C50  41.89,42.86 180 top
C51  24.75,30.8 270 top
C52  44.11,30.8 270 top
C53  9.51,27.94 180 top
C54  46.81,14.76 270 top
C55  5.7,13.97 180 top
C56  19.03,13.97 0 top
C57  31.89,13.97 0 top
C58  49.83,13.97 180 top
C59  12.36,2.7 90 top
C60  35.06,2.7 90 top
C61  23.79,2.7 90 top
D1  40.62,100.97 90 top
D2  56.18,100.97 270 top
D3  25.7,57.63 90 top
H2  39.98,31.12 0 top
H3  19.03,31.11 0 top
IC1  6.97,100.33 270 top
IC2  37.76,82.55 0 top
IC3  51.26,74.93 0 top
IC4  18.39,73.66 270 top
IC5  38.72,68.26 90 top
IC6  10.14,45.72 270 top
IC7  30.78,45.72 270 top
IC8  49.51,45.72 270 top
IC9  41.1,45.4 0 top
J1  6.65,20.95 180 top
J2  18.08,20.95 180 top
J3  29.51,20.95 180 top
J4  40.94,20.95 180 top
J5  52.37,20.95 180 top
J6  6.65,6.35 180 top
J7  18.08,6.35 180 top
J8  29.51,6.35 180 top
J9  40.94,6.35 180 top
J10  52.37,6.35 180 top
JP1  1.89,104.78 0 top
JP2  57.13,104.78 0 top
JP3  1.89,2.54 0 top
JP4  57.13,2.54 0 top
JP5  2.52,54.61 270 bottom
JP6  2.52,85.09 90 bottom
JP8  48.24,102.23 90 bottom
L1  16.49,104.78 180 top
L2  40.62,97 90 top
L3  56.18,96.84 90 top
L4  31.89,90.49 270 top
L5  53.95,80.8 0 top
LED1  29.51,92.71 0 top
LED2  29.51,87.31 0 top
LED3  29.51,81.92 0 top
LED4  29.51,76.52 0 top
LED5  29.51,71.12 0 top
LED6  29.51,65.72 0 top
LED7  29.51,60.33 0 top
LED8  29.51,54.93 0 top
Q1  6.28,74.3 90 top
R1  11.41,88.27 180 top
R2  47.6,88.27 180 top
R3  35.86,87.31 0 top
R4  16.01,83.19 180 top
R5  10.78,75.09 180 top
R6  10.78,74.14 180 top
R7  10.14,60.96 180 top
R8  48.88,60.96 180 top
R9  5.22,55.24 90 top
R10  5.22,52.55 90 top
R11  38.24,51.75 90 top
R12  39.67,51.75 90 top
R13  37.45,48.9 90 top
R14  17.44,48.26 0 top
R15  23.48,48.26 180 top
R16  50.46,47.94 180 top
R17  4.74,47.62 270 top
R18  15.54,47.62 270 top
R19  25.38,47.62 270 top
R20  36.17,47.62 270 top
R21  42.52,47.31 90 top
R22  43.79,47.31 270 top
R23  23.48,46.99 180 top
R24  2.2,46.35 270 top
R25  3.47,46.35 270 top
R26  16.81,46.35 270 top
R27  37.45,46.35 270 top
R28  55.22,46.04 270 top
R29  23.48,44.45 180 top
R30  3.47,43.81 90 top
R31  4.74,43.81 90 top
R32  15.54,43.81 90 top
R33  16.81,43.81 90 top
R34  25.38,43.81 90 top
R35  36.17,43.81 90 top
R36  37.45,43.81 90 top
R37  43.79,43.5 270 top
R38  23.48,43.18 180 top
R39  37.45,41.59 270 top
R40  3.47,41.27 270 top
R41  16.81,41.27 270 top
R42  10.14,36.83 180 top
R43  29.51,36.83 180 top
R44  48.88,36.83 180 top
R45  35.54,13.65 270 top
R46  44.11,12.7 0 top
R47  55.54,12.7 0 top
R48  21.89,12.38 270 top
R49  25.7,12.38 270 top
R50  13.47,11.91 180 top
R51  23.48,11.11 90 top
SW1  25.06,100.33 0 top
SW2  33.95,100.33 0 top
U$1  [FCC_MEDIUM]  50.14,15.24 0 bottom
U$2  [ROHS_BIG]  39.19,7.62 0 bottom
U$3  [CE_MEDIUM]  50.46,7.62 0 bottom

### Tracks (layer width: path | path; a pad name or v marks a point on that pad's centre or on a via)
+3V3  (via drill 0.5)
  Top 0.254: IC5.17 37.76,71.08 37.76,70.33 37.45,70.01 36.02,70.01 35.78,70.25 IC5.20 | IC5.20 35.77,71.12 | IC5.20 35.78,71.36 | C25.1 C26.1 17.92,66.36 17.64,66.63 IC4.17 17.64,70.69 18.71,71.75 18.71,75.09 v19.19,75.56 | v16.01,75.56 15.64,75.93 | 15.64,75.93 IC4.48 15.64,79.8 16.01,80.17 16.01,80.77 C10.1 | v34.27,74.3 34.27,74.93 34.75,75.41 C16.+ 36.46,75.22 34.78,73.54 C17.1 34.9,72.9 34.9,72.71 35.78,71.83 IC5.20 | 17.8,94.97 C6.1 18.08,94.3 16.81,93.03 14.74,93.03 13.79,92.08 13.79,86.84 16.61,84.01 R4.1 16.05,82.62 C9.1 C10.1 | C10.1 | IC5.20 35.78,71.52 | v41.89,73.03 41.89,72.07 41.65,71.83 IC5.11 | 15.64,75.93 15.17,76.41 IC4.1
  Top 0.406: LED5.A 29.51,69.69 26.02,66.2 26.02,63.82 | LED6.A 27.6,63.82 26.02,63.82 | 26.02,63.82 26.02,59.69 26.8,58.91 D3.2 28.08,58.58 | LED7.A 29.51,59.37 28.71,58.58 28.08,58.58 | LED8.A 29.51,56.52 28.08,57.94 28.08,58.58
  Top 0.813: LED4.A LED3.A LED2.A 29.51,89.79 | IC1.3 10.14,97.79 12.71,95.22 C3.+ 15.84,94.92 15.89,94.97 C6.1 18.11,94.93 v21.57,94.93 21.55,94.92 | 29.51,89.79 L4.2 | LED1.A 29.51,89.79
  Bottom 0.254: v34.27,74.3 41.25,74.3 41.89,73.66 v41.89,73.03 | v19.19,75.56 v16.01,75.56
  Bottom 0.406: 29.51,74.3 v34.27,74.3
  Bottom 0.813: LED4.A 29.51,74.3 LED5.A | LED1.A 27.29,94.93 v21.57,94.93
+3V3_A  (via drill 0.5)
  Top 0.254: v14.59,67.47 14.59,63.5 12.64,61.55 R7.P$1 | IC5.1 34.63,65.42 C27.1 33.76,65.37 v33.32,64.93 | R1.P$1 13.79,81.15 13.79,79.69 11.89,77.79 9.51,77.79 7.6,79.69 3.79,79.69 2.68,78.58 2.68,70.33 5.06,67.94 9.19,67.94 10.14,68.9 v10.14,70.8 C19.1 C20.1 12.08,71.95 12.54,72.41 IC4.9 15.68,72.41 v16.01,72.07 | IC4.24 21.26,69.29 21.5,69.53 22.68,69.53 | v20.14,72.07 | 22.68,69.53 v20.14,72.07 | R7.P$1 12.68,53.92 | R7.P$1 12.64,52.19 9.79,49.34 C36.1 9.79,46.64 8.87,45.72 IC6.4 | IC4.25 22.68,70.87 22.68,69.53 | v22.52,65.56 22.73,65.77 C24.1 C23.1 22.68,68.15 22.68,69.53 | IC5.8 C28.1 | C44.1 IC7.4 v29.51,45.72
  Top 0.406: R8.P$1 51.41,54 v51.41,63.02 51.41,66.83 50.59,67.66 50.59,68.9 | 32.05,28.26 23.32,28.26 v20.46,25.4 | 32.05,28.26 50.78,28.26 51.38,28.85 R44.P$1 | R43.P$1 32.05,30.09 32.05,28.26 | v57.13,47.62 57.13,43.81 55.86,42.55 55.86,36.83 57.13,35.56 v57.13,34.61 | C30.+ 41.07,62.23 | v42.84,63.02 41.92,62.1 C30.+ | C28.1 40.3,63.94 40.3,63.5 40.94,62.87 C30.+ | 50.59,68.9 C22.+ | C22.+ 50.62,69.56 | R2.P$1 49.99,81.15 49.99,80.01 48.88,78.9 48.88,78.58 | 48.4,78.11 48.88,78.58 | 48.4,78.11 48.4,70.48 49.35,69.53 C22.+ | IC3.1 49.83,72.95 49.83,72.07 50.59,71.31 50.59,68.9 | 48.4,78.11 48.88,78.58
  Bottom 0.254: 33.79,65.41 v33.32,64.93 | v10.14,70.8 13.47,67.47 v14.59,67.47 | v29.51,45.72 29.51,37.47 32.01,34.97 R43.P$1 | v20.14,72.07 v16.01,72.07
  Bottom 0.356: 17.28,25.4 v20.46,25.4
  Bottom 0.406: v51.41,63.02 v42.84,63.02 40.46,65.41 33.79,65.41 32.36,66.83 24.75,66.83 23.48,65.56 v22.52,65.56 | R44.P$1 51.41,30.16 52.68,30.16 v57.13,34.61 | v57.13,47.62 57.13,50.8 53.97,53.96 R8.P$1 | 17.28,25.4 12.64,30.04 R42.P$1
ADC_FM
  Top 0.254: IC4.22 20.14,68.1 20.62,67.63 20.62,55.24 25.38,50.48 25.38,50.16 25.38,49.69 R19.1 C40.2 27.21,47.67 IC7.1
ADC_GATE
  Top 0.254: IC4.21 19.64,67.97 20.14,67.47 20.14,54.29 15.54,49.69 15.54,49.37 R18.1 C39.2 13.71,47.67 IC6.14
ADC_HARMONICS
  Top 0.254: C41.2 R20.1 | C41.2 34.9,48.26 | 33.48,48.27 32.35,48.27 28.4,52.23 26.33,52.23 23.48,55.09 23.48,63.02 24.9,64.45 24.9,66.52 26.02,67.63 26.02,70.48 24.09,72.41 IC4.28 | C41.2 34.85,48.27 33.48,48.27 | 33.48,48.27 33.49,48.26 IC7.14
ADC_MODEL  (via drill 0.5)
  Top 0.254: v11.73,43.02 11.25,43.5 11.25,48.1 12.68,49.53 14.11,49.53 19.19,54.61 | v9.19,43.02 9.19,43.18 8.6,43.77 IC6.7 6.57,43.77 C46.2 R31.1 | 19.19,54.61 19.19,59.37 19.19,67.15 18.64,67.69 IC4.19 | 19.19,54.61
  Bottom 0.254: v9.19,43.02 v11.73,43.02
ADC_MORPH
  Top 0.254: R35.1 C49.2 34.35,43.77 IC7.8 32.41,43.77 32.36,43.81 31.41,44.77 31.41,48.58 28.24,51.75 26.17,51.75 23,54.93 23,63.34 24.43,64.77 24.43,66.67 25.54,67.79 25.54,70.33 23.96,71.91 IC4.27
ADC_TIMBRE
  Top 0.254: IC4.20 19.14,67.83 19.66,67.31 19.66,54.45 15.22,50.01 14.74,49.53 14.27,49.05 12.84,49.05 11.73,47.94 11.73,47.62 11.73,44.13 12.09,43.77 IC6.8 13.36,43.77 13.92,43.22 C47.2 R32.1
ADC_TRIG  (via drill 0.5)
  Top 0.254: v7.28,50.16 7.42,50.02 IC6.1 6.92,47.67 6.33,48.26 6.33,48.23 C38.2 R17.1 | IC4.18 18.14,67.56 18.71,66.99 18.71,63.82 18.71,54.77 | v13.63,50.48 14.43,50.48 18.71,54.77 | 18.71,54.77
  Bottom 0.254: v7.28,50.16 7.6,50.48 v13.63,50.48
ADC_V_OCT
  Top 0.254: IC4.26 23.82,71.41 25.06,70.17 25.06,67.94 23.95,66.83 23.95,64.93 22.52,63.5 22.52,54.77 26.02,51.28 28.08,51.28 30.78,48.58 30.78,44.77 29.82,43.81 29.78,43.77 IC7.7 27.21,43.77 C48.2 R34.1
AREF_-10  (via drill 0.5)
  Top 0.254: v22.84,45.72 22.82,45.7 | v24.11,41.59 25.38,40.32 35.86,40.32 v36.17,40.64 | 4.73,45.7 v4.74,45.72 3.51,45.72 R25.2 R30.2 | R33.2 R26.2 16.77,45.72 v15.54,45.72 | R23.2 22.84,46.95 v22.84,45.72 | R29.2 22.84,44.48 v22.84,45.72 | R27.2 | R27.2 R36.2 | R27.2 37.41,45.72 v36.17,45.72 | R27.2 37.49,45.7 39.68,45.7 39.98,45.4 41.57,45.4 42.05,44.93 IC9.2 42.05,43.98 42.52,43.5 42.52,42.9 | 42.52,42.9 C50.1 | 42.52,42.9 R37.2
  Bottom 0.254: v24.11,41.59 22.84,42.86 v22.84,45.72 v15.54,45.72 14.27,44.45 6.01,44.45 v4.74,45.72 | v36.17,40.64 v36.17,45.72
DAC_BCK
  Top 0.254: IC5.13 40.3,71.08 40.3,70.17 38.71,68.58 35.86,68.58 | IC4.29 25.5,72.91 25.7,72.71 32.36,72.71 33.63,71.44 33.63,69.85 34.9,68.58 35.86,68.58 | 35.86,68.58 35.54,68.58 35.38,68.58
DAC_DIN
  Top 0.254: IC5.14 39.67,71.08 39.67,70.17 38.56,69.06 35.06,69.06 34.11,70.01 34.11,71.6 32.52,73.18 26.49,73.18 26.02,73.66 25.77,73.91 IC4.31
DAC_LRCK
  Top 0.254: IC5.15 39.03,70.17 38.4,69.53 35.22,69.53 34.59,70.17 34.59,71.75 32.68,73.66 26.65,73.66 26.17,74.14 | 26.17,74.14 | 26.17,74.14 25.9,74.41 IC4.32
FM_IN
  Top 0.254: 31.09,16.51 J3.P3 | 31.09,16.51 39.98,25.4 53.32,25.4 53.64,25.72 53.64,31.11 53.32,31.43 51.1,31.43 47.6,34.92 47.6,37.15 45.7,39.05 24.11,39.05 21.89,41.27 21.89,47.94 22.21,48.26 R15.2 | C57.1 31.09,14.03 31.09,16.51
FREQ_ATT  (via drill 0.5)
  Top 0.254: R43.P$2 29.51,31.43 28.24,32.7 24.75,32.7 | C51.1 24.75,32.7 | v20.93,52.86 20.3,52.23 20.3,37.15 24.75,32.7 | v16.49,57.63 17.28,58.42 17.28,61.91 15.54,63.66 15.54,66.52 16.64,67.62 IC4.15
  Bottom 0.254: v20.93,52.86 19.03,52.86 16.49,55.4 v16.49,57.63
FREQ_POT
  Top 0.254: IC4.10 12.84,71.91 12.36,71.44 12.36,70.48 9.35,67.47 4.9,67.47 2.2,70.17 2.2,78.74 6.33,82.87 11.09,82.87 11.41,82.55 R1.P$2 11.41,79.09 C11.1
GATE_IN
  Top 0.254: R14.2 18.04,47.59 17.76,47.31 17.76,39.21 17.6,39.05 17.6,35.72 14.9,33.02 14.9,27.94 10.78,23.81 10.78,15.88 10.14,15.24 10.14,11.11 9.82,10.79 5.38,10.79 4.43,9.84 4.43,5.08 6.33,3.17 9.51,3.17 11.41,5.08 14.9,5.08 J7.P3 18.13,1.85 C61.1
GATE_IN1
  Top 0.254: R24.2 2.2,45.24 2.68,44.77 2.68,33.97 3.47,33.18 3.47,5.08 J6.P3 7.76,1.91 8.24,2.38 9.66,2.38 10.2,1.85 C59.1
GND  (via drill 0.5)
  Top 0.254: 26.49,56.82 26.49,56.83 26.64,56.83 D3.1
  other vias: 30.78,88.58 36.81,88.9 34.9,81.6 36.81,63.82 14.27,45.72 39.51,72.71 42.84,65.72 40.94,57.47 35.54,58.42 24.11,45.72 34.9,45.72 43.79,45.4 53.64,49.21 9.03,72.55 27.92,105.41 18.08,97.47 53.95,44.13 49.35,75.09 54.43,64.14 7.44,78.26 5.22,70.33 6.17,45.72 29.82,46.99 17.76,63.34 19.35,71.12 21.57,64.61 23.63,69.22 21.57,57.78 24.11,49.85 18.71,51.44 21.73,40 17.76,55.88 15.86,53.98 16.81,79.38 20.3,76.2 9.82,41.59 39.98,42.86 40.62,91.44 23.48,91.44 13.63,59.05 12.36,66.52 19.66,73.34 31.09,67.94 31.09,64.45 1.25,7.62 1.25,17.78 1.25,27.94 1.25,38.1 1.25,99.06 7.6,105.41 19.03,105.41 38.08,105.41 57.76,88.9 42.52,82.23 48.56,58.74 57.76,78.74 57.76,64.14 57.76,58.42 57.76,38.1 57.76,27.94 57.76,17.78 57.76,7.62 8.87,1.27 27.92,1.27 38.08,1.27 48.24,1.27 20.93,93.34 48.56,64.77 50.46,58.74 35.54,53.5 40.94,53.5 17.12,85.72 18.39,92.71 16.81,73.03 51.89,43.18 49.51,46.35 10.3,76.2 13,100.33 22.68,51.28 8.87,46.99 7.6,51.75 9.82,45.4 13.95,24.13 40.94,75.25 40.62,73.34 50.46,64.77 23.48,82.55 26.81,53.34 24.9,61.59 27.92,50.01 49.35,76.36 54.11,75.09 54.11,73.82 54.11,76.36 49.35,77.63 54.11,72.55 54.11,71.28 52.84,71.28 51.57,71.28
  pour Top: 59.03,106.68 59.03,0 -0.02,0 -0.02,106.68
  pour Bottom: 59.03,106.68 59.03,0 -0.02,0 -0.02,106.68
HARMONICS_IN  (via drill 0.5)
  Top 0.254: v39.03,41.27 39.35,40.96 46.65,40.96 49.51,38.1 49.51,35.88 52.05,33.34 54.27,33.34 55.54,32.07 55.54,18.1 53.95,16.51 J5.P3 52.37,15.66 C58.1 | 37.48,49.53 R13.2 37.8,49.49 38.24,49.05 38.24,47.78 v39.03,46.99
  Bottom 0.254: v39.03,41.27 v39.03,46.99
HARMONICS_POT  (via drill 0.5)
  Top 0.254: IC4.12 14.14,70.68 13.79,70.33 13.47,70.33 9.66,66.52 4.58,66.52 1.25,69.85 1.25,79.06 7.28,85.09 v12.68,85.09 | v24.59,85.09 24.59,93.82 26.33,95.57 38.08,95.57 40.62,93.03 42.21,93.03 45.86,89.38 45.86,85.25 47.6,83.5 R2.P$2 47.6,79.09 C12.1
  Bottom 0.254: v12.68,85.09 13.47,85.09 14.11,84.45 23.95,84.45 v24.59,85.09
LEDS_SCK
  Top 0.254: 35.54,79.77 IC2.3 35.54,77.15 35.54,76.83 34.43,75.72 32.84,74.14 26.81,74.14 26.33,74.61 26.04,74.91 IC4.33
LEDS_SIN
  Top 0.254: IC4.35 25.67,75.91 26.97,74.61 32.68,74.61 33.95,75.88 34.9,76.83 IC2.2
LEDS_SS  (via drill 0.5)
  Top 0.254: 26.65,75.56 27.13,75.09 29.67,75.09 30.62,75.09 32.52,75.09 33.48,76.04 | 26.65,75.56 | 26.65,75.56 25.8,76.41 IC4.36 | 33.48,76.04 | 33.48,76.04 33.95,76.52 v33.95,77.47 | v36.65,77.47 36.17,77.95 IC2.4
  Bottom 0.254: v33.95,77.47 v36.65,77.47
MODEL_IN
  Top 0.254: R40.2 3.47,33.97 4.11,33.34 4.11,19.05 J1.P3 6.65,14.07 C55.1
MORPH_ATT  (via drill 0.5)
  Top 0.254: R44.P$2 48.88,31.43 47.92,32.38 44.11,32.38 | 44.11,32.38 C52.1 | v15.38,56.83 15.38,57.94 16.81,59.37 | 16.81,59.37 | 16.81,59.37 16.81,61.75 15.06,63.5 15.06,66.67 16.14,67.76 IC4.14 | v21.41,51.75 20.78,51.12 20.78,37.78 24.9,33.66 42.84,33.66 44.11,32.38
  Bottom 0.254: v21.41,51.75 20.78,51.75 20.14,52.39 18.87,52.39 16.01,55.24 16.01,56.2 v15.38,56.83 | v15.38,56.83 15.54,56.67 | v15.38,56.83
MORPH_IN
  Top 0.254: J4.P3 46.81,16.51 | 46.81,16.51 50.46,16.51 51.73,17.78 53,17.78 54.91,19.68 54.91,31.75 53.95,32.7 51.73,32.7 48.88,35.56 48.88,37.78 46.33,40.32 38.71,40.32 38.04,40.99 R39.2 | C54.1 | 46.81,16.51 C54.1
MORPH_POT  (via drill 0.5)
  Top 0.254: IC4.11 13.13,71.41 12.84,71.12 12.84,70.33 9.51,66.99 4.74,66.99 1.73,70.01 1.73,78.9 7.44,84.61 11.73,84.61 12.36,83.98 v13.32,83.98 | v25.54,83.98 25.54,85.57 25.06,86.04 25.06,93.66 26.49,95.09 37.92,95.09 40.46,92.55 42.05,92.55 45.38,89.22 45.38,86.68 43.48,84.77 43.48,80.01 47.29,76.2 47.29,69.85 49.51,67.63 49.51,56.2 48.88,55.56 R8.P$2 48.88,51.79 C34.1
  Bottom 0.254: v13.32,83.98 23,83.98 | 23,83.98 | 23,83.98 v25.54,83.98
N$1
  Top 0.61: 15.49,103.05 L1.2
  Top 0.813: 15.49,103.05 C1.1 15.41,102.87 IC1.1
N$2
  Top 0.254: 45.06,56.67 47.13,58.74 47.13,68.26 45.7,69.69 45.7,75.56 41.44,79.83 IC2.12 | 45.06,56.67 | 45.06,56.67 43.79,55.4 34.75,55.4 34.27,54.93 LED8.GREEN_C
N$3
  Top 0.254: J6.P2 10.78,9.53 12.87,11.62 R50.2
N$4
  Top 0.254: R24.1 R25.1 3.54,47.02 R17.2 C38.1 IC6.2
N$5
  Top 0.254: LED8.RED_C 28.24,53.66 32.05,53.66 32.84,54.45 34.43,54.45 34.9,54.93 43.95,54.93 44.91,55.88 45.22,56.2 47.6,58.58 47.6,68.42 46.18,69.85 46.18,75.72 42.05,79.85 42.05,80.49 41.89,80.64 40.94,80.64 40.62,80.33 IC2.11
N$6
  Top 0.254: C29.1 35.54,62.39 35.54,63.82 36.02,64.29 36.44,64.72 IC5.2
N$7
  Top 0.254: R5.1 | R5.1 11.89,75.09 12.36,74.61 13.32,74.61 13.52,74.41 IC4.5
N$8
  Top 0.254: R6.1 | R6.1 13.16,74.14 13.38,73.91 IC4.6
N$9
  Top 0.254: 39.98,79.77 IC2.10 39.98,79.06 40.14,78.9 41.73,78.9 45.22,75.41 45.22,69.53 46.65,68.1 46.65,58.9 43.64,55.88 34.9,55.88 32.05,58.74 LED7.GREEN_C
N$10
  Top 0.254: LED7.RED_C 27.92,61.28 32.52,61.28 33,60.8 33,58.58 35.22,56.36 43.48,56.36 45.54,58.42 46.18,59.05 46.18,67.94 44.75,69.37 44.75,75.25 41.57,78.42 39.83,78.42 39.35,78.9 IC2.9
N$11
  Top 0.254: LED6.GREEN_C 33,66.67 39.35,66.67 41.1,68.42 42.68,68.42 44.27,70.01 44.27,75.09 41.41,77.95 39.67,77.95 38.71,78.9 IC2.8
N$12
  Top 0.254: LED4.RED_C 27.92,75.56 29.51,75.56 30.46,75.56 32.36,75.56 33,76.2 33,80.33 33.95,81.28 33.95,82.23 34.27,82.55 39.83,82.55 41.25,83.98 IC2.13
N$13
  Top 0.254: LED6.RED_C 30.14,68.9 32.68,68.9 34.43,67.15 39.19,67.15 40.94,68.9 42.52,68.9 43.79,70.17 43.79,74.93 41.25,77.47 39.19,77.47 38.08,78.58 IC2.7
N$14
  Top 0.254: LED4.GREEN_C 32.05,80.01 33.48,81.44 33.48,82.39 34.11,83.03 39.51,83.03 40.62,84.14 IC2.14
N$15
  Top 0.254: LED5.GREEN_C 32.68,70.48 32.68,69.53 34.59,67.63 39.03,67.63 40.78,69.37 42.37,69.37 43.32,70.33 43.32,74.77 41.1,76.99 39.03,76.99 37.45,78.58 IC2.6
N$16
  Top 0.254: C29.2 37.29,63.02 37.73,63.47 IC5.4
N$17  (via drill 0.5)
  Top 0.254: v31.09,80.33 31.73,80.33 33,81.6 33,82.55 33.95,83.5 39.19,83.5 39.98,84.3 IC2.15
  Bottom 0.254: v31.09,80.33 28.55,80.33 LED3.RED_C
N$18
  Top 0.254: LED3.GREEN_C 32.05,82.23 33.79,83.98 38.87,83.98 39.35,84.45 IC2.16
N$19
  Top 0.254: LED2.RED_C 26.97,91.12 26.02,92.08 26.02,93.03 27.13,94.14 36.97,94.14 38.87,92.23 38.87,86.68 38.74,86.54 38.71,86.52 IC2.17
N$20
  Top 0.254: LED2.GREEN_C 32.05,85.72 33.32,84.45 37.45,84.45 37.92,84.45 38.08,84.61 IC2.18
N$21
  Top 0.254: LED1.RED_C 27.92,93.66 36.81,93.66 38.4,92.08 38.4,87 37.45,86.04 IC2.19
N$22
  Top 0.254: LED5.RED_C 28.08,72.23 32.21,72.23 33.16,71.28 33.16,69.69 34.75,68.1 38.87,68.1 40.62,69.85 42.21,69.85 42.84,70.48 42.84,74.61 40.94,76.52 38.87,76.52 36.81,78.58 IC2.5
N$23
  Top 0.254: LED1.GREEN_C 36.97,92.71 37.13,92.71 37.92,91.92 37.92,87.15 36.81,86.04 IC2.20
N$24
  Top 0.254: J3.P2 25.7,20.32 R49.1
N$25
  Top 0.254: J2.P2 21.89,20.32 R48.1
N$26
  Top 0.254: J4.P2 35.54,18.73 R45.1
N$27
  Top 0.254: IC2.24 34.27,86.04 34.11,86.2 C8.1
  Top 0.406: C8.1 33.99,87 33.63,87 33,87.63 33,89.22 33.6,89.82 C7.+
  Top 0.813: C7.+ 32.86,91.39 L4.1
N$28
  Top 0.254: R14.1 16.84,46.99 R26.1 15.61,46.95 R18.2 C39.1 | C39.1 14.23,46.99 | IC6.13 C39.1
N$29
  Top 0.254: R5.2 5.54,75.09 5.08,75.55 Q1.3 5.1,76.52 C14.2
N$30
  Top 0.254: R38.1 R29.1 24.07,44.41 R34.2 C48.1 26.68,44.45 26.71,44.42 IC7.6
N$31  (via drill 0.5)
  Top 0.254: v9.82,16.51 10.3,16.99 10.3,24.13 14.43,28.26 14.43,33.34 16.97,35.88 16.97,39.05 16.81,39.21 R41.2 | C56.1 18.08,14.07 J2.P3
  Bottom 0.254: v9.82,16.51 J2.P3
N$32
  Top 0.254: C49.1 R35.2 36.24,44.41 R36.1 R39.1 | C49.1 34.87,44.45 | R39.1 | IC7.9 C49.1
N$33
  Top 0.254: 5.1,52.07 R10.1 2.64,51.95 JP5.2
N$34
  Top 0.254: R15.1 R23.1 24.11,47.02 R19.2 C40.1 IC7.2
N$35
  Top 0.254: R6.2 7.92,74.14 7.44,73.66 7.44,72.14 Q1.1 7.48,70.41 C21.2
N$36
  Top 0.254: J7.P2 20.3,9.53 21.29,10.51 R51.1
N$37
  Top 0.254: R40.1 R30.1 4.67,44.41 R31.2 C46.1 6.05,44.45 6.08,44.42 IC6.6
N$38
  Top 0.406: L3.2 D2.A
N$39
  Top 0.254: R41.1 R33.1 16.74,43.22 R32.2 C47.1 14.23,44.45 14.2,44.42 IC6.9
N$40
  Top 0.406: L5.2 54.59,80.87 54.59,89.22 52.68,91.12 45.38,91.12 41.57,94.93 40.3,94.93 39.67,95.57 39.67,97.16 40.21,97.7 L2.2
  Top 0.61: L2.2 D1.C 39.34,99.06 38.08,100.33 21.89,100.33 19.03,103.19 17.95,103.19 C2.1 | 17.49,103.27 17.39,103.37 L1.1
  Top 0.813: 17.49,103.27 C2.1
N$41
  Top 0.254: C41.1 R20.2 36.24,46.95 R27.1 R13.1 | C41.1 34.87,46.99 | IC7.13 C41.1
N$42
  Top 0.406: 51.41,78.74 C13.1 51.41,78.74 | 51.41,78.74 51.41,79.69 52.53,80.8 L5.1 | IC3.3 52.68,73.02 52.68,74.3 53,74.61 53,77.15 51.41,78.74
N$43  (via drill 0.5)
  Top 0.254: IC5.6 39.03,64.29 38.71,63.98 38.71,58.1 v38.24,57.63 | R11.2 v38.24,53.66
  Bottom 0.254: v38.24,53.66 v38.24,57.63
N$46
  Top 0.254: R21.2 42.08,47.91 42.05,47.94 41.73,47.94 39.19,50.48 38.56,50.48 38.24,50.8 R11.1 C33.1
N$47
  Top 0.254: R16.2 46.65,47.94 46.02,48.58 41.89,48.58 39.67,50.8 R12.1 C35.1
N$48
  Top 0.254: IC5.5 38.4,64.45 38.24,64.29 38.24,61.28 38.08,61.12 37.6,61.12 37.28,60.8 C31.1
N$51
  Top 0.254: 5.18,54.61 R9.1 2.56,54.65 JP5.1
N$54
  Top 0.254: 37.11,71.12 IC5.18 37.1,72.96 C18.1
N$55  (via drill 0.5)
  Top 0.254: IC5.7 39.67,65.39 39.67,64.14 39.19,63.66 39.19,58.1 v39.67,57.63 | R12.2 v39.67,53.66
  Bottom 0.254: v39.67,53.66 v39.67,57.63
N$56
  Top 0.61: JP8.9 43.16,102.87 | 43.16,102.87 JP8.10 | D1.A 43.16,102.87
N$58
  Top 0.254: R28.2 C43.1 53.91,45.4 IC8.6 52.43,45.4 51.73,45.4 51.06,46.07 R16.1
N$60
  Top 0.254: IC8.7 53.01,46.05 53.64,46.67 53.92,46.67 C43.2 R28.1 55.89,46.64 56.18,46.35 56.18,44.45 54.91,43.18 53.32,43.18 50.78,40.64 50.78,36.51 52.68,34.61 54.91,34.61 56.81,32.7 56.81,17.46 56.39,17.04 R47.2
N$62
  Top 0.254: R21.1 R22.2 C42.1 45.73,46.05 IC8.2
N$63
  Top 0.254: R22.1 C42.2 45.1,47.94 45.7,47.94 46.58,47.06 IC8.1 47.9,46.7 48.24,46.35 48.24,40.32 50.14,38.42 50.14,36.2 52.37,33.97 54.59,33.97 56.18,32.38 56.18,17.78 51.1,12.7 R46.2
N$64
  Top 0.406: D2.C 54.91,102.87 54.27,103.5 JP8.2 JP8.1
N$65
  Top 0.254: J9.P3 43.26,4.23 R46.1
N$68
  Top 0.254: R3.1 35.22,87.28 35.22,86.68 34.9,86.36 IC2.23
N$69
  Top 0.254: J10.P3 54.69,4.23 R47.1
NORMALIZATION_PROBE  (via drill 0.5)
  Top 0.254: v26.97,69.37 26.49,68.9 26.49,67.47 25.38,66.36 25.38,63.5 23.95,62.07 23.95,58.9 24.6,58.25 D3.3 24.59,57.62 24.59,56.2 25.38,55.4 v25.38,54.61 | v20.93,73.5 21.03,73.41 IC4.30 | v18.87,49.85 19.35,49.37 19.35,35.4 16.49,32.54 16.49,23.18 13.95,20.64 13.95,12.03 R50.1 15.22,11.91 16.33,10.79 20.3,10.79 21.29,11.78 R48.2 21.96,11.71 R51.2 23.55,11.78 R49.2 25.73,11.75 26.65,11.75 27.6,10.79 34.11,10.79 35.54,12.22 R45.2 | v25.38,54.61
  Bottom 0.254: v18.87,49.85 22.52,49.85 25.38,52.7 v25.38,54.61 | v20.93,73.5 22.36,73.5 24.11,71.75 25.7,70.17 26.49,69.37 v26.97,69.37
RESET  (via drill 0.5)
  Top 0.254: v15.86,73.98 15.29,73.41 IC4.7 | C15.1 14.07,76.96 v14.43,77.31 14.43,77.47 15.06,78.11 15.06,80.01 15.38,80.33 15.38,83.15 R4.2 15.41,84.26 15.22,84.45 13.32,86.36 13.32,90.17 10.78,92.71 JP6.4
  Bottom 0.254: v15.86,73.98 14.43,75.41 v14.43,77.31
RX
  Top 0.254: IC4.46 16.64,76.68 17.76,75.56 17.76,72.23 16.65,71.12 15.62,71.12 14.35,69.85 13.63,69.85 7.28,63.5 7.28,59.69 5.22,57.63 R9.2
SW_1
  Top 0.254: SW1.3 SW1.4 27.56,98.07 20.93,91.44 19.66,91.44 18.71,90.49 18.71,90.17 18.71,89.53 18.71,79.38 18.14,78.81 IC4.43
SW_2
  Top 0.254: SW2.4 SW2.3 28.68,96.04 26.17,96.04 21.09,90.96 19.82,90.96 19.19,90.33 19.19,79.22 | IC4.42 18.64,78.67 19.19,79.22 | 19.19,79.22
SWCLK  (via drill 0.5)
  Top 0.254: v21.73,88.27 21.78,88.21 21.14,87.58 IC4.37
  Bottom 0.254: v21.73,88.27 19.35,88.27 17.12,90.49 4.27,90.49 3.95,90.17 JP6.3
SWDIO  (via drill 0.5)
  Top 0.254: IC4.34 21.73,75.41 21.41,75.72 21.41,76.68 21.73,76.99 21.73,86.52 v22.36,87.15
  Bottom 0.254: 5.22,90.01 | 5.22,90.01 16.81,90.01 19.03,87.79 20.93,87.79 21.57,87.15 v22.36,87.15 | 5.22,90.01 2.84,87.63 JP6.2
TIMBRE_ATT
  Top 0.254: IC4.16 17.14,67.49 16.01,66.36 16.01,63.82 17.76,62.07 17.76,57.47 17.44,57.15 | 17.44,57.15 | 17.44,57.15 14.11,53.82 14.11,53.02 10.78,49.69 10.78,48.9 10.78,35.24 10.14,34.61 R42.P$2 10.14,27.98 C53.1
TIMBRE_POT
  Top 0.254: IC4.13 15.64,68.85 15.22,68.42 14.27,68.42 13.47,67.63 13.47,65.88 10.14,62.55 R7.P$2 10.14,51.79 C32.1
TX
  Top 0.254: 17.12,77.89 IC4.45 17.14,76.81 18.24,75.72 18.24,71.91 | 18.24,71.91 16.97,70.64 15.78,70.64 14.51,69.37 13.79,69.37 7.76,63.34 7.76,59.37 6.17,57.78 6.17,53.5 5.82,53.15 R10.2 | 18.24,71.91
V_OCT_IN
  Top 0.254: R38.2 22.82,43.18 22.82,41.61 24.75,39.69 46.02,39.69 48.24,37.47 48.24,35.24 51.41,32.07 53.64,32.07 54.27,31.43 54.27,20 52.68,18.41 51.41,18.41 50.14,17.14 42.21,17.14 41.57,17.78 39.98,17.78 39.35,17.14 39.35,14.29 38.08,13.02 38.08,3.81 36.12,1.85 C60.1 29.56,1.85 J8.P3
VCC
  Top 0.254: IC8.8 52.35,46.78 52.4,46.83 C37.1 | 43.48,96.52 C4.+
  Top 0.406: 43.48,96.52 43.48,93.98 45.7,91.76 53,91.76 55.54,89.22 55.54,53.02 52.4,49.88 C37.1 | L2.1 40.73,96.2 41.57,96.2 41.89,96.52 C4.+
VEE  (via drill 0.5)
  Top 0.254: IC8.4 46.58,44.38 46.33,44.13 45.1,44.13 C45.2 | v45.06,42.86 C45.2 | R37.1 43.86,44.17 C45.2
  Top 0.406: C5.- 53,96.51 | v55.22,48.58 55.22,51.75 56.18,52.7 56.18,89.53 53,92.71 53.01,92.72 C5.- | C5.- 54.27,96.52 54.85,95.94 L3.1
  Bottom 0.406: v55.22,48.58 49.51,42.86 v45.06,42.86

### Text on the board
bNames: +12V | GND | GND | GND | -12V | Red Stripe | Plaits | cc-by-sa Émilie Gillet | 2017. v5
tStop: Plaits | cc-by-sa | 2017. v5 | Émilie Gillet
